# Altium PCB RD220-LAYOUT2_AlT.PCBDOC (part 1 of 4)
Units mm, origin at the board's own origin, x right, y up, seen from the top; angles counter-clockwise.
Board outline 250 x 145 mm, 4 copper layers (TOP, Mid-Layer 1, Mid-Layer 2, BOTTOM), stack 0.711 mm thick; 497 components, 207 nets, 1178 pads, 436 vias.
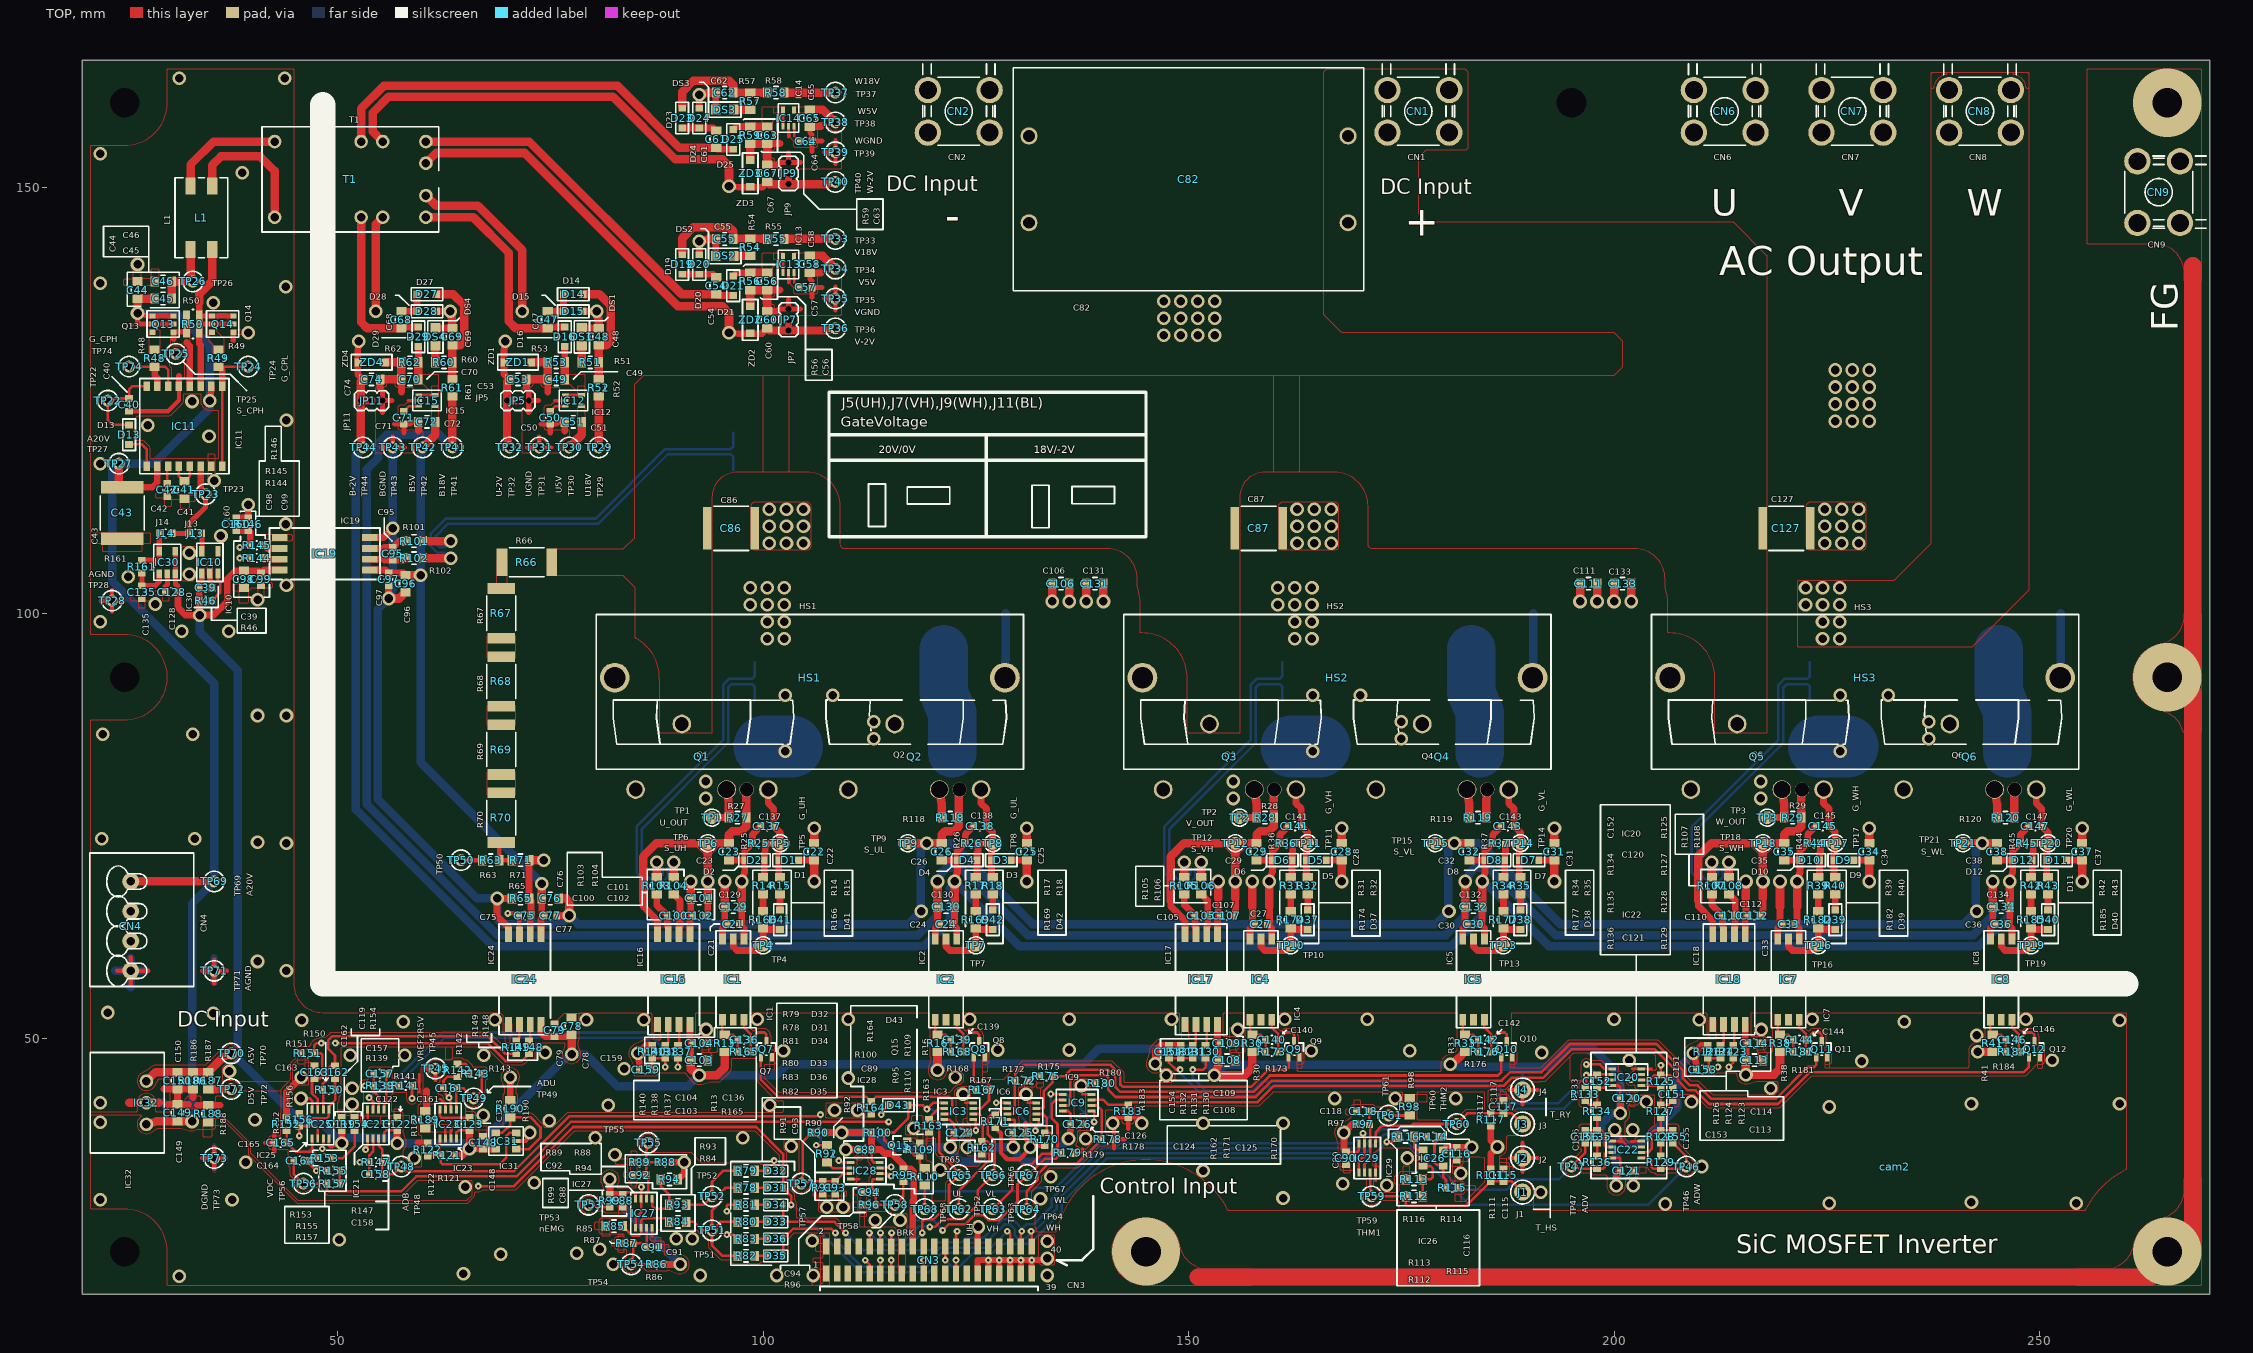
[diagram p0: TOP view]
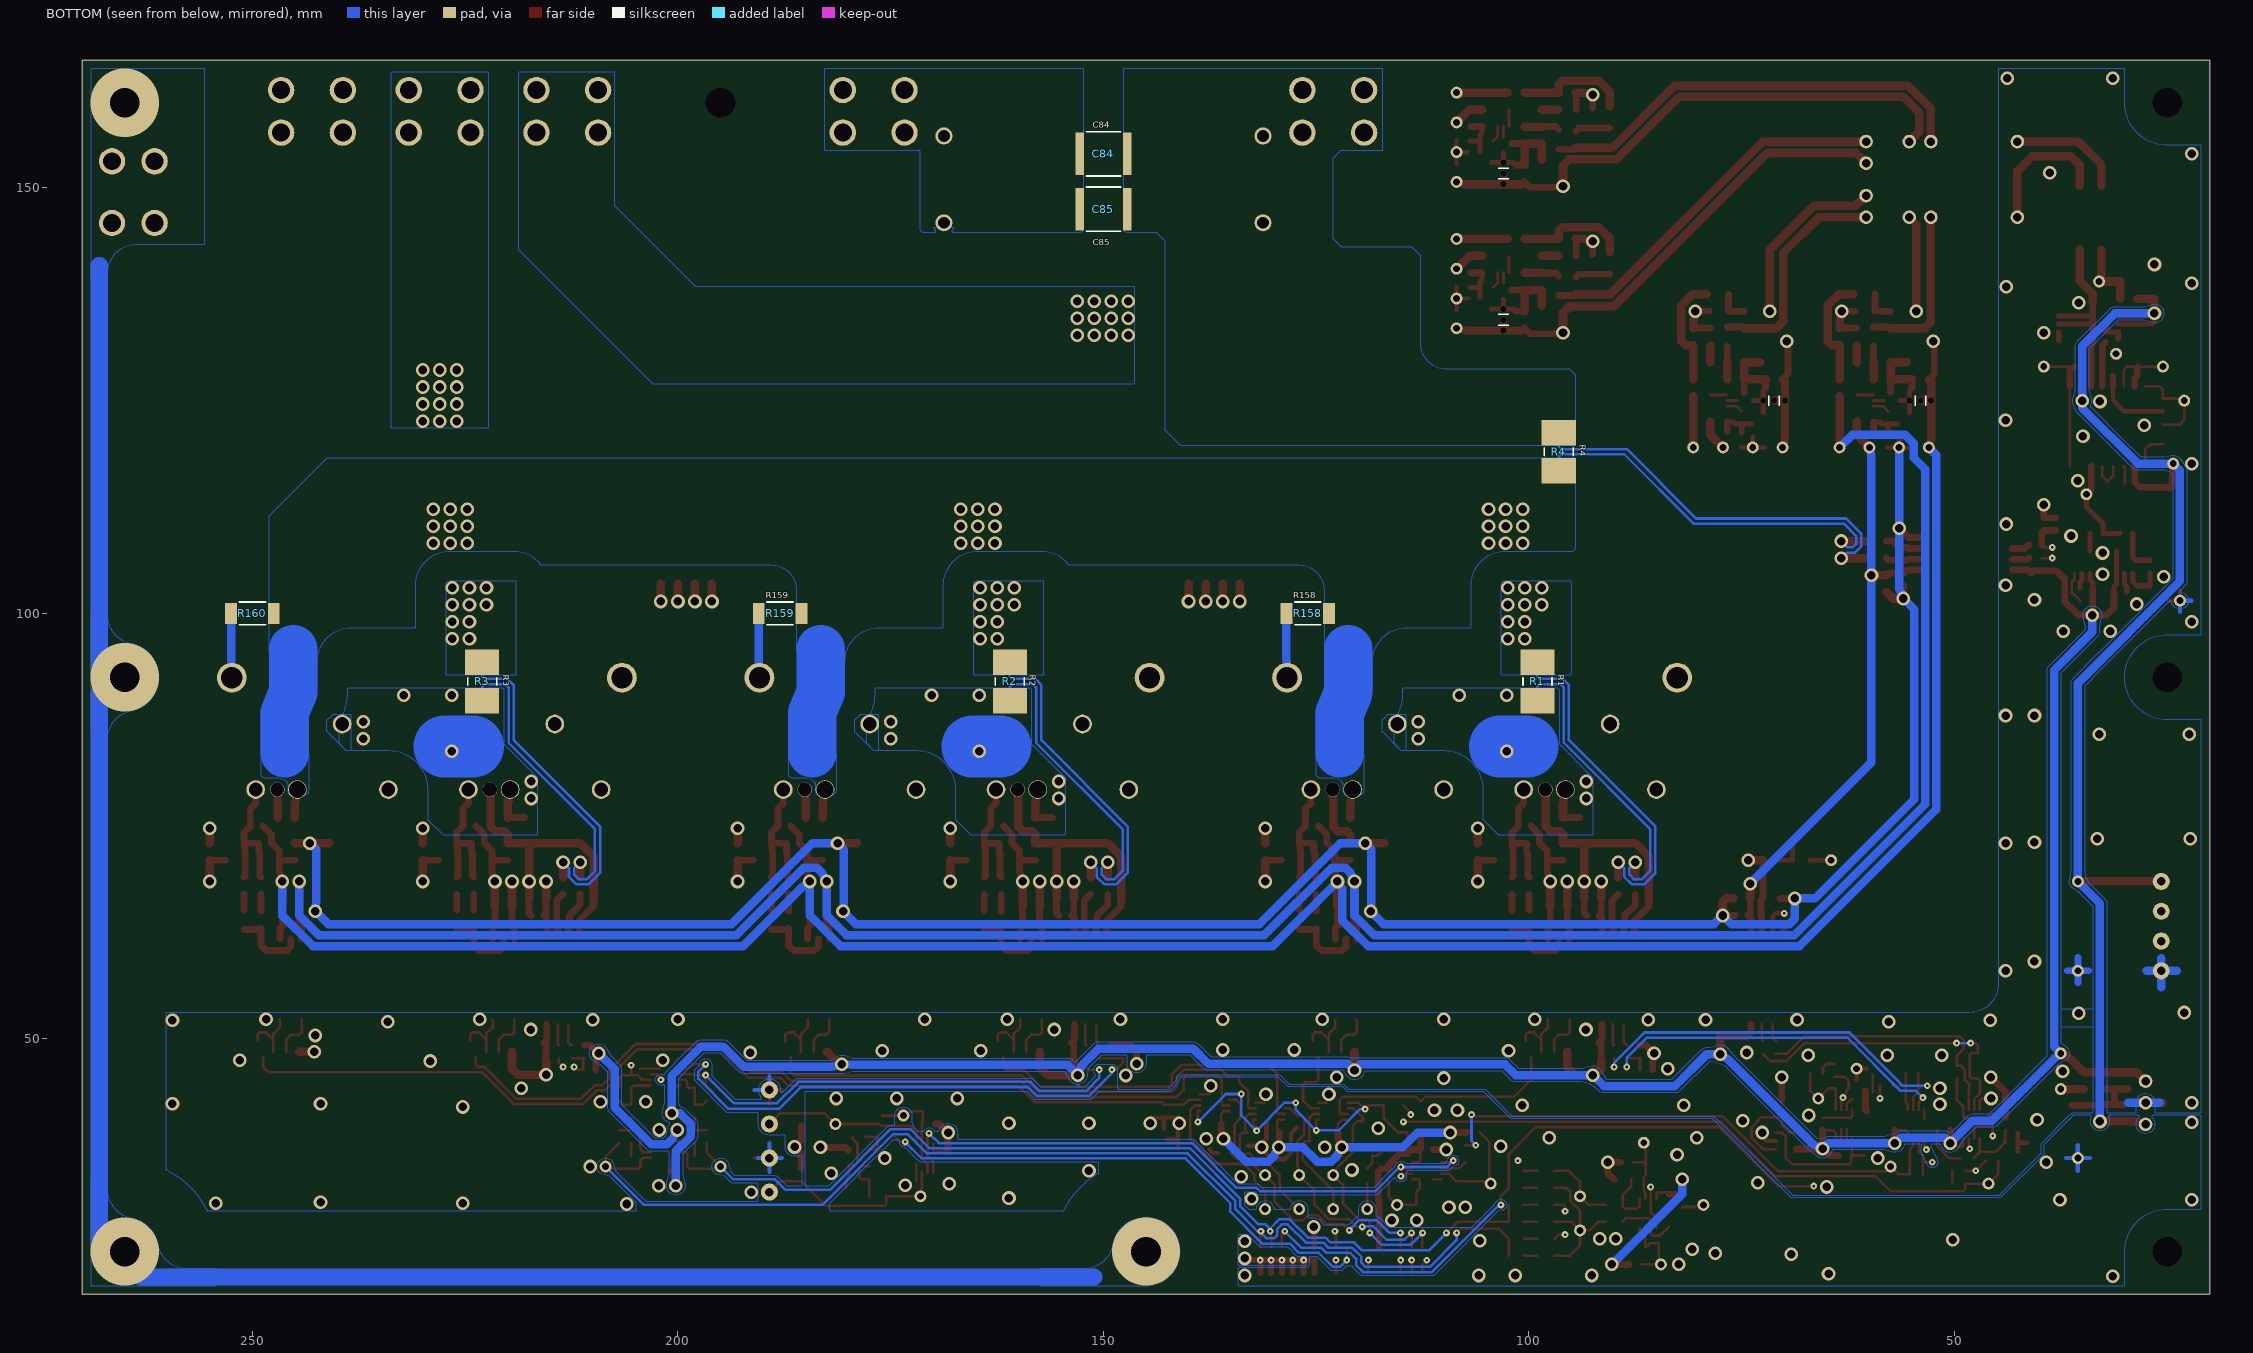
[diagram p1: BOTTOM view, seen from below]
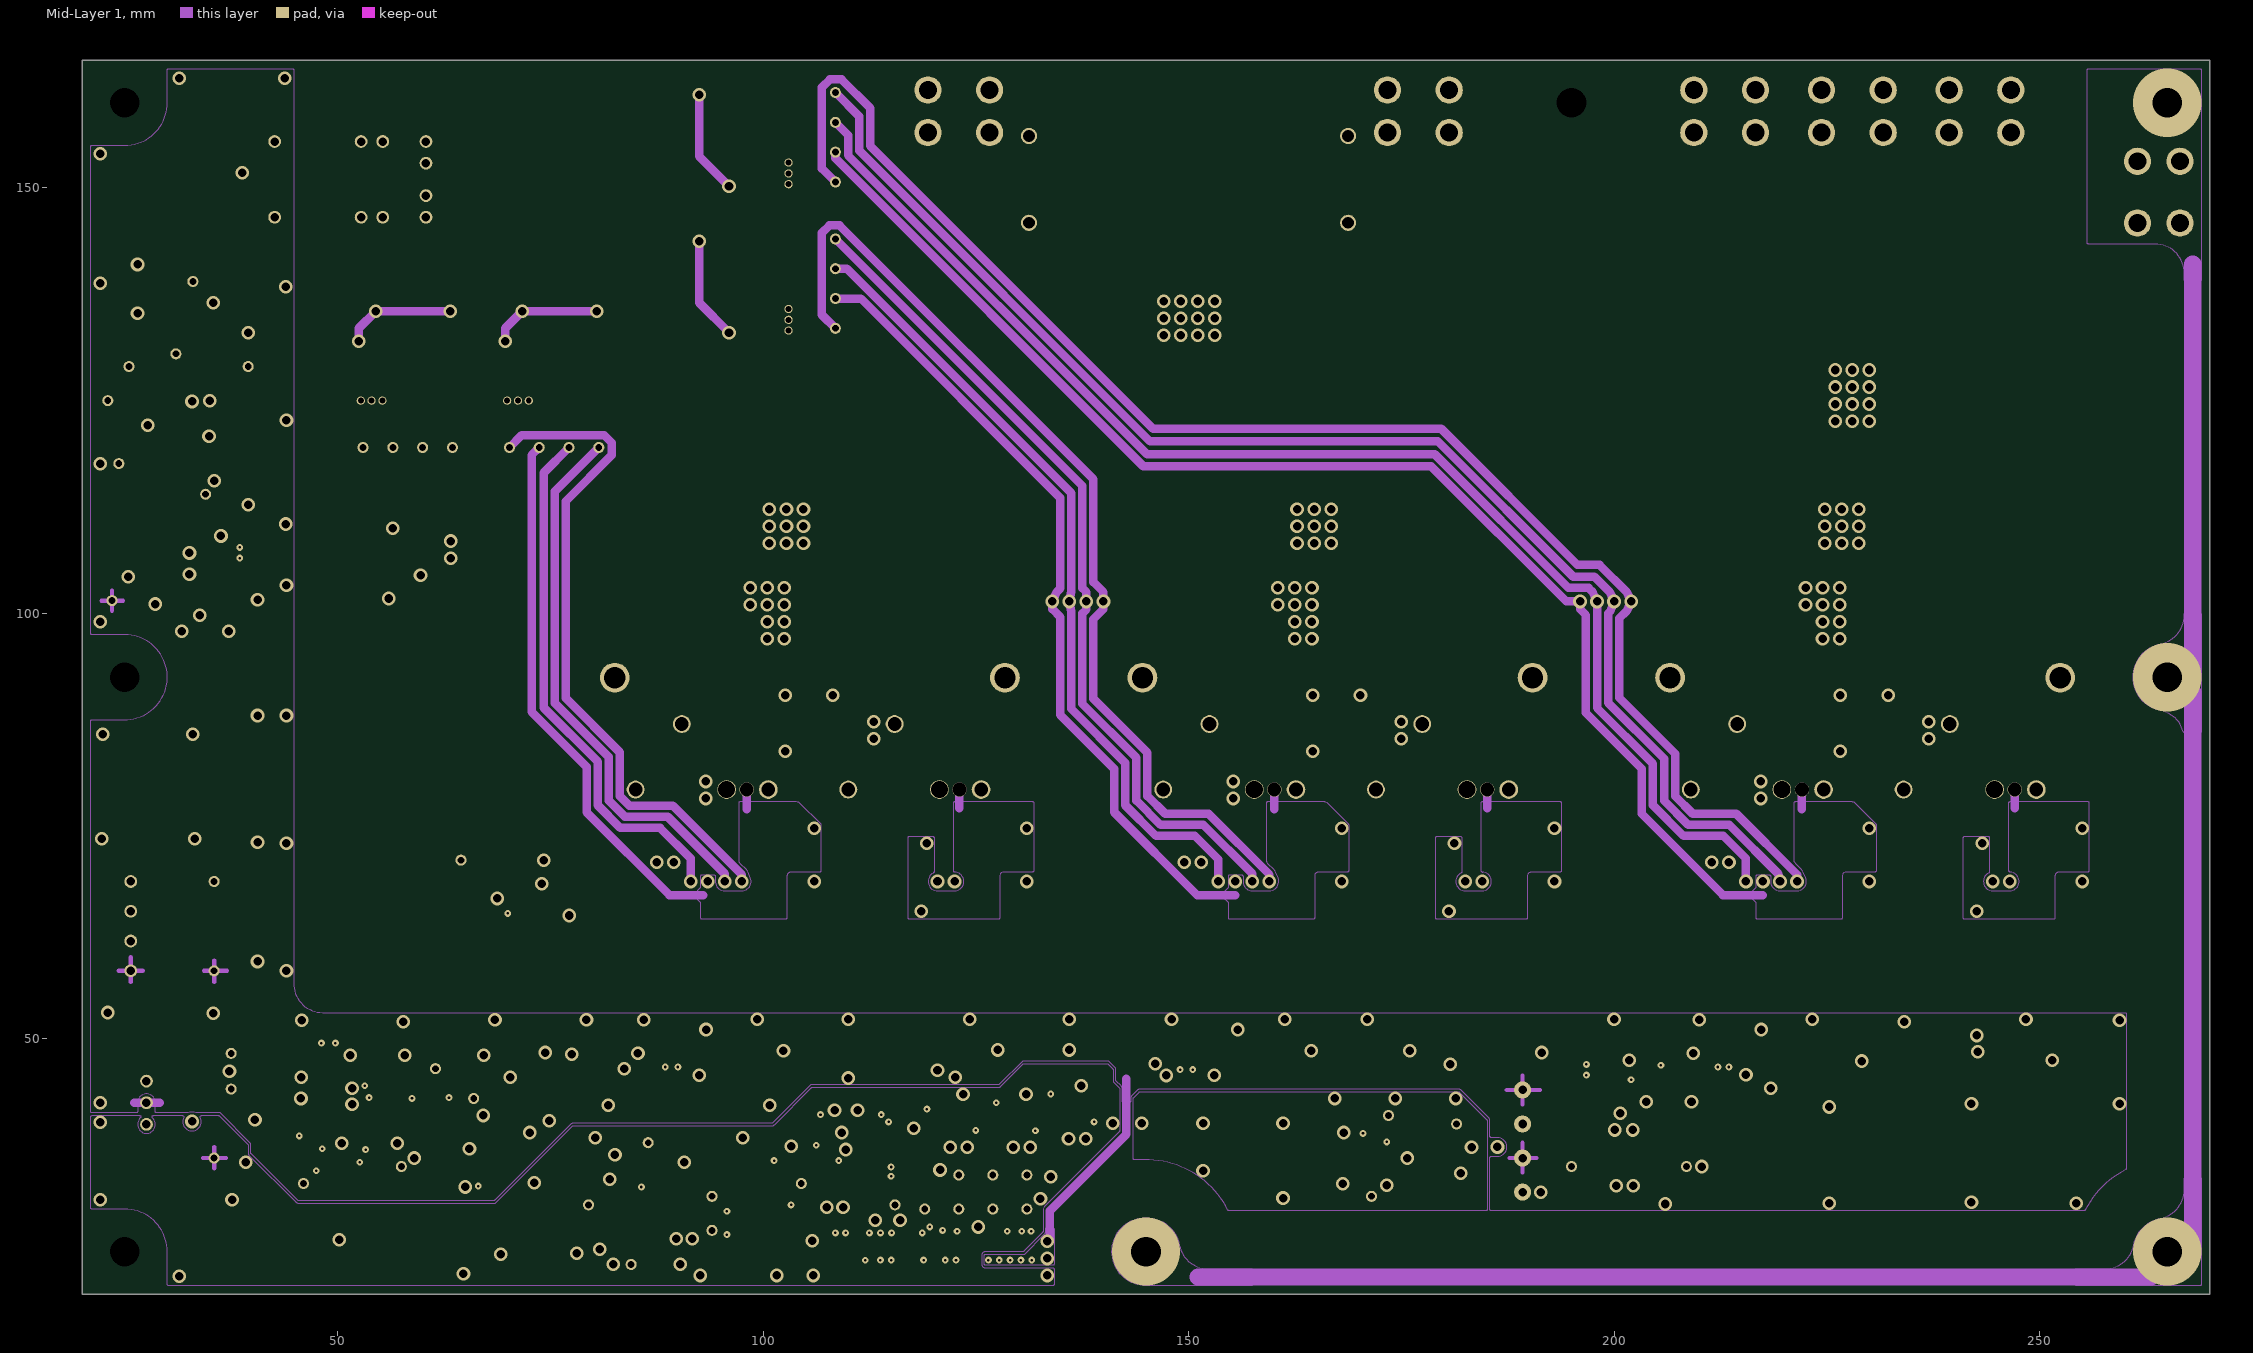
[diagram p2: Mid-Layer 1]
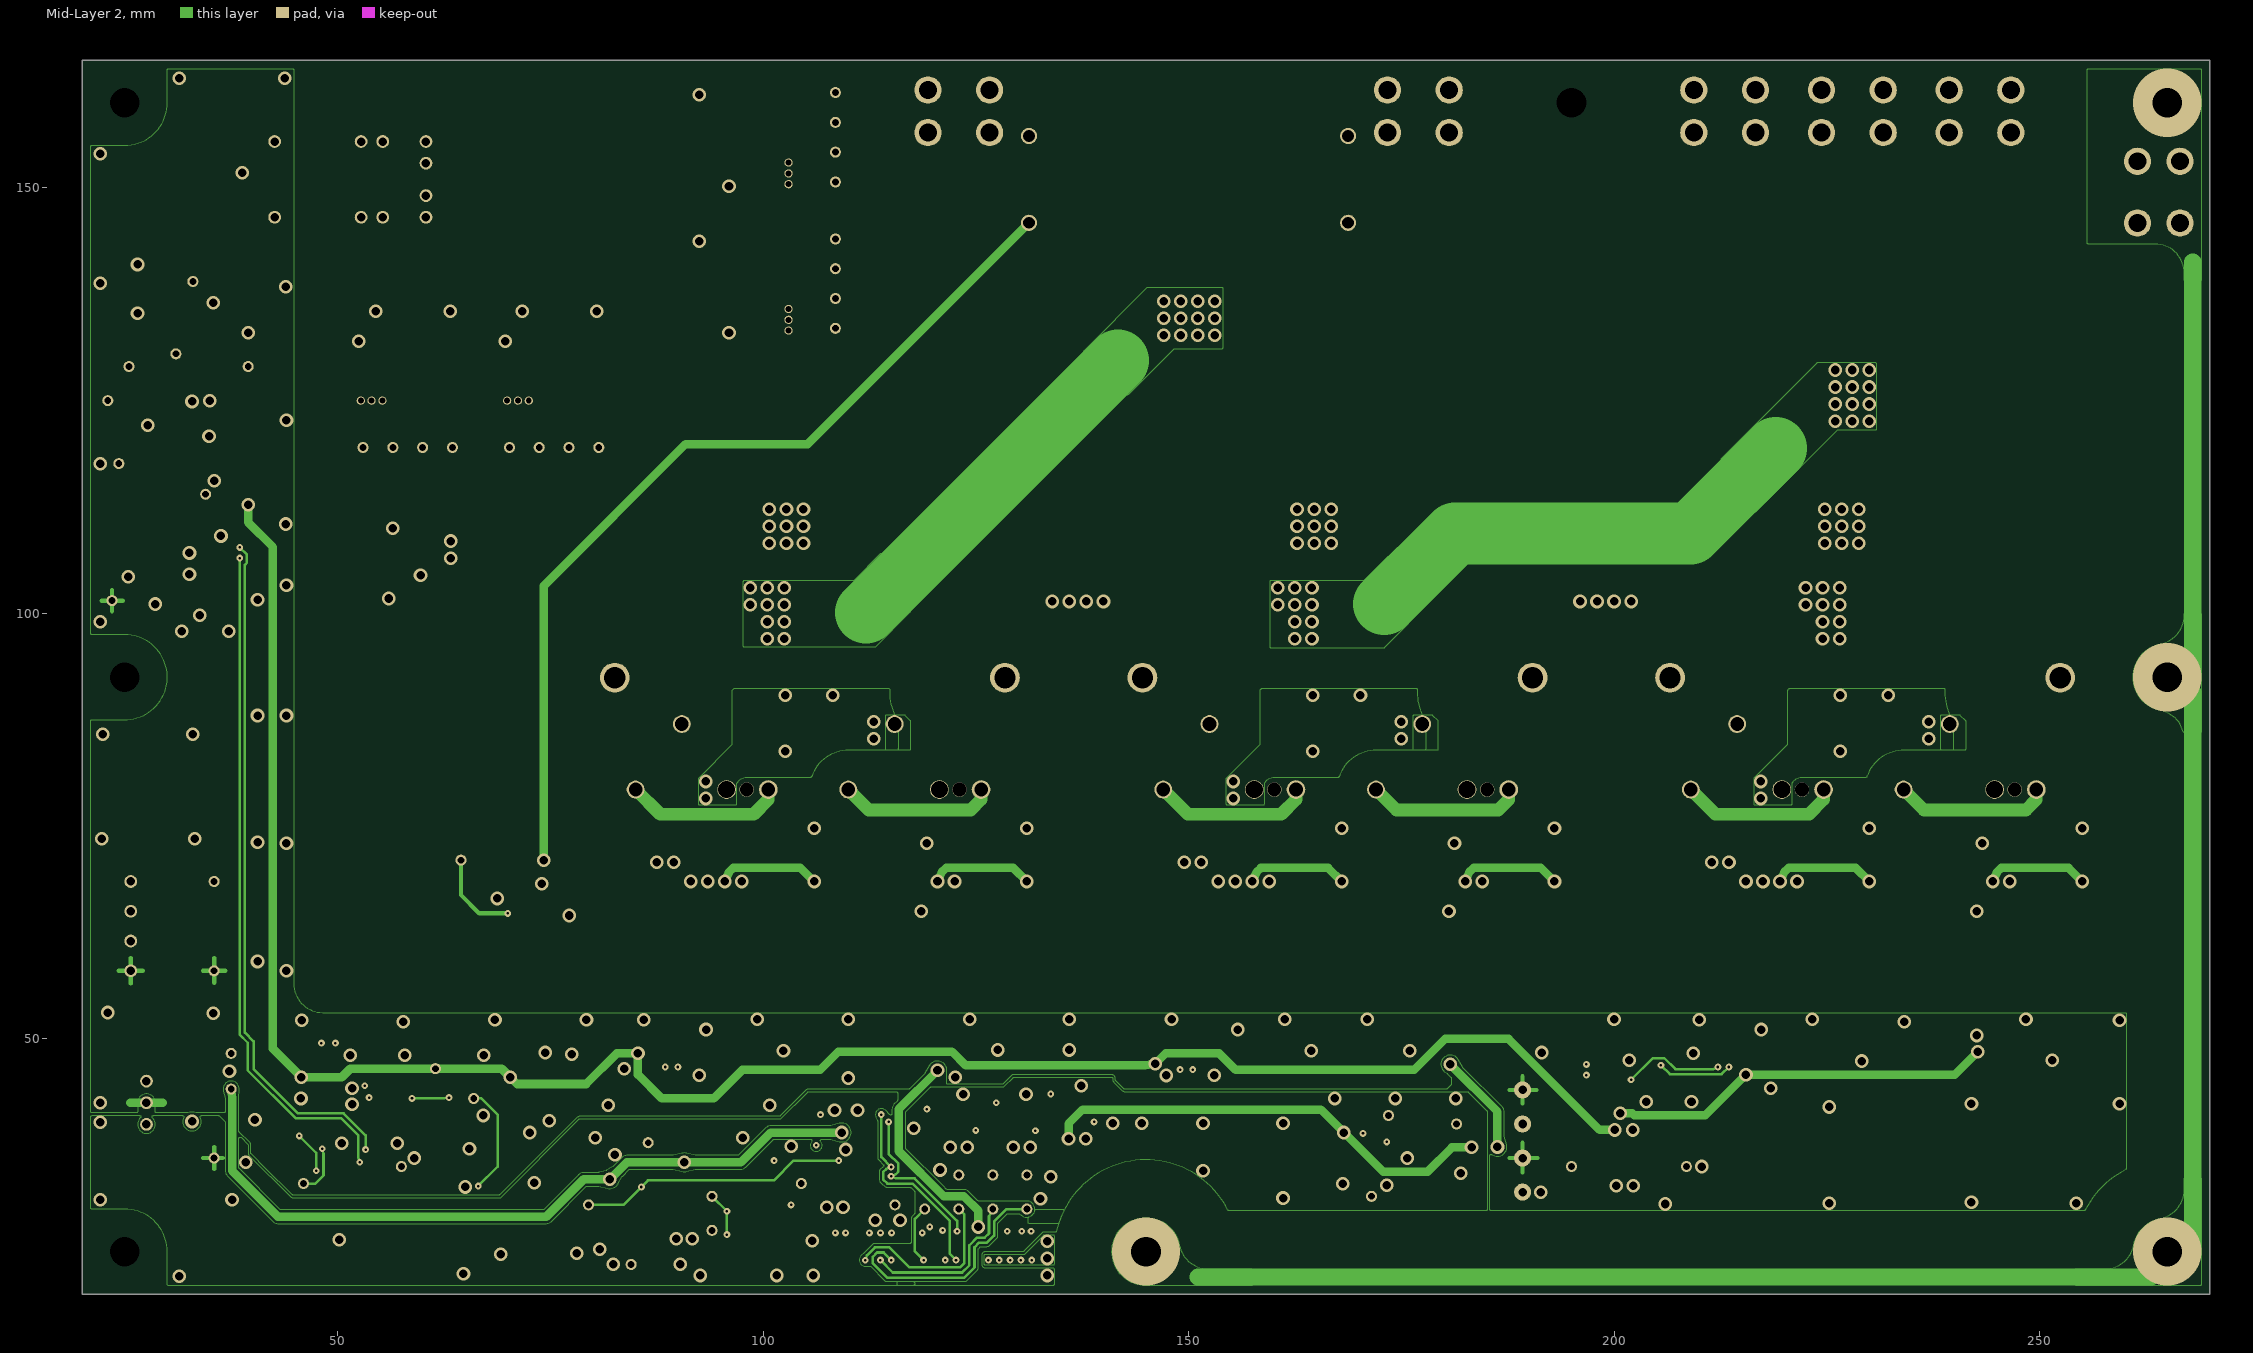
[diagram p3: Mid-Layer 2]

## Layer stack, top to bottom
Top Solder: solder mask 0.0102, Solder Resist, Dk 3.5
TOP: signal copper (thickness not stored)
Mid-Layer 1: signal copper 0.0356
Dielectric2: dielectric 0.32, FR-4, Dk 4.8
Mid-Layer 2: signal copper 0.0356
Dielectric3: dielectric 0.32, FR-4, Dk 4.8
BOTTOM: signal copper (thickness not stored)
Bottom Solder: solder mask 0.0102, Solder Resist, Dk 3.5

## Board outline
20,20 20,165 270,165 270,20

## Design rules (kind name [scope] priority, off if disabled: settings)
AssemblyTestPointUsage [All] p0: scope1count=1 scope1_0_kind=Board scope1_0_value=Board scope2count=1 scope2_0_kind=Board scope2_0_value=Board commentlength=0
AssemblyTestpoint [All] p0: scope1count=1 scope1_0_kind=Board scope1_0_value=Board scope2count=1 scope2_0_kind=Board scope2_0_value=Board commentlength=0
Clearance [All] p0: scope1count=1 scope1_0_kind=Board scope1_0_value=Board scope2count=1 scope2_0_kind=Board scope2_0_value=Board commentlength=0 gap=0.3
Clearance [All] p1: gap=0.3 ignorepadtopadclearanceinfootprint=TRUE except(0.5: Arc-Hole Track-Hole SMDPad-SMDPad SMDPad-Hole THPad-Hole Fill-Hole Poly-Hole Region-Hole Text-Hole; 0.75: Via-Hole; 1: SMDPad-THPad THPad-THPad)
ComponentClearance [All] p0: scope1count=1 scope1_0_kind=Board scope1_0_value=Board scope2count=1 scope2_0_kind=Board scope2_0_value=Board commentlength=0 gap=0.254 collisioncheckmode=3
DiffPairsRouting [All] p0: scope1count=1 scope1_0_kind=Board scope1_0_value=Board scope2count=1 scope2_0_kind=Board scope2_0_value=Board commentlength=0
FabricationTestPointUsage [All] p0: scope1count=1 scope1_0_kind=Board scope1_0_value=Board scope2count=1 scope2_0_kind=Board scope2_0_value=Board commentlength=0 valid=0 allowmultiple=FALSE
FabricationTestpoint [All] p0: scope1count=1 scope1_0_kind=Board scope1_0_value=Board scope2count=1 scope2_0_kind=Board scope2_0_value=Board commentlength=0 side=3 testpointundercomponent=TRUE minsize=1.016 maxsize=2.54 preferedsize=1.524 minholesize=0 maxholesize=1.016 preferedholesize=0.813 testpointgrid=0.025
FanoutControl Fanout_BGA [All] p0 off: scope1count=1 scope1_0_kind=Board scope1_0_value=Board scope2count=1 scope2_0_kind=Board scope2_0_value=Board commentlength=69 // Protel DXP Scope 1 Expression Was: IsBGA   Fanout_BGA (Default Rule)
FanoutControl Fanout_LCC [All] p0 off: scope1count=1 scope1_0_kind=Board scope1_0_value=Board scope2count=1 scope2_0_kind=Board scope2_0_value=Board commentlength=69 // Protel DXP Scope 1 Expression Was: IsLCC   Fanout_LCC (Default Rule)
FanoutControl Fanout_SOIC [All] p0 off: scope1count=1 scope1_0_kind=Board scope1_0_value=Board scope2count=1 scope2_0_kind=Board scope2_0_value=Board commentlength=71 // Protel DXP Scope 1 Expression Was: IsSOIC   Fanout_SOIC (Default Rule)
FanoutControl Fanout_Small [All] p0 off: scope1count=1 scope1_0_kind=Board scope1_0_value=Board scope2count=1 scope2_0_kind=Board scope2_0_value=Board commentlength=84 // Protel DXP Scope 1 Expression Was: (CompPinCount < 5)   Fanout_Small (Default Rule)
FanoutControl Fanout_Default [All] p0: scope1count=1 scope1_0_kind=Board scope1_0_value=Board scope2count=1 scope2_0_kind=Board scope2_0_value=Board commentlength=30 // Fanout_Default (Default Rule)
Height [All] p0: scope1count=1 scope1_0_kind=Board scope1_0_value=Board scope2count=1 scope2_0_kind=Board scope2_0_value=Board commentlength=0
HoleSize [All] p0: scope1count=1 scope1_0_kind=Board scope1_0_value=Board scope2count=1 scope2_0_kind=Board scope2_0_value=Board commentlength=0 absolutevalues=TRUE maxlimit=100 minlimit=0.001 maxpercent=80.000 minpercent=20.000
HoleSize [All] p1: absolutevalues=TRUE maxlimit=100 minlimit=0.001 maxpercent=80.000 minpercent=20.000
HoleToHoleClearance [All] p0: scope1count=1 scope1_0_kind=Board scope1_0_value=Board scope2count=1 scope2_0_kind=Board scope2_0_value=Board commentlength=0
HoleToHoleClearance [All] p1: gap=0.7 allowstackedmicrovias=FALSE
LayerPairs [All] p0: scope1count=1 scope1_0_kind=Board scope1_0_value=Board scope2count=1 scope2_0_kind=Board scope2_0_value=Board commentlength=0 enforce=TRUE
MinimumSolderMaskSliver [All] p0: scope1count=1 scope1_0_kind=Board scope1_0_value=Board scope2count=1 scope2_0_kind=Board scope2_0_value=Board commentlength=0
MinimumSolderMaskSliver [All] p1: minsoldermaskwidth=0.2
NetAntennae [All] p0: scope1count=1 scope1_0_kind=Board scope1_0_value=Board scope2count=1 scope2_0_kind=Board scope2_0_value=Board commentlength=0
NetAntennae [All] p1: netantennaetolerance=100
PasteMaskExpansion [All] p0: scope1count=1 scope1_0_kind=Board scope1_0_value=Board scope2count=1 scope2_0_kind=Board scope2_0_value=Board commentlength=0 expansion=0
PlaneClearance [All] p0: scope1count=1 scope1_0_kind=Board scope1_0_value=Board scope2count=1 scope2_0_kind=Board scope2_0_value=Board commentlength=0 clearance=0.001
PlaneClearance [All] p1: clearance=0.001
PlaneConnect [All] p0: scope1count=1 scope1_0_kind=Board scope1_0_value=Board scope2count=1 scope2_0_kind=Board scope2_0_value=Board commentlength=0 planeconnectstyle=Direct reliefexpansion=0.508 reliefentries=4 reliefconductorwidth=0.254 reliefairgap=0.254
PlaneConnect [All] p1: planeconnectstyle=Direct reliefexpansion=0.508 reliefentries=4 reliefconductorwidth=0.254 reliefairgap=0.254
PolygonConnect [All] p0: scope1count=1 scope1_0_kind=Board scope1_0_value=Board scope2count=1 scope2_0_kind=Board scope2_0_value=Board commentlength=0 connectstyle=Direct reliefconductorwidth=0.254 reliefentries=4 polygonreliefangle="90 Angle"
PolygonConnect [All] p1: connectstyle=Direct reliefconductorwidth=0.254 reliefentries=4 polygonreliefangle="90 Angle" airgapwidth=0.254
RoutingCorners [All] p0: scope1count=1 scope1_0_kind=Board scope1_0_value=Board scope2count=1 scope2_0_kind=Board scope2_0_value=Board commentlength=0 cornerstyle=45-Degree minsetback=2.54 maxsetback=2.54
RoutingLayers [All] p0: scope1count=1 scope1_0_kind=Board scope1_0_value=Board scope2count=1 scope2_0_kind=Board scope2_0_value=Board commentlength=0 top layer=Automatic mid layer 1=Automatic mid layer 2=Automatic bottom layer=Automatic
RoutingPriority [All] p0: scope1count=1 scope1_0_kind=Board scope1_0_value=Board scope2count=1 scope2_0_kind=Board scope2_0_value=Board commentlength=0
RoutingTopology [All] p0: scope1count=1 scope1_0_kind=Board scope1_0_value=Board scope2count=1 scope2_0_kind=Board scope2_0_value=Board commentlength=0 topology=Shortest
RoutingVias [All] p0: scope1count=1 scope1_0_kind=Board scope1_0_value=Board scope2count=1 scope2_0_kind=Board scope2_0_value=Board commentlength=0 holewidth=0.1 width=0.1 viastyle="Through Hole" minholewidth=0.001 minwidth=0.001 maxholewidth=100 maxwidth=100
RoutingVias [All] p1: holewidth=0.1 width=0.1 viastyle="Through Hole" minholewidth=0.001 minwidth=0.001 maxholewidth=100 maxwidth=100
ShortCircuit [All] p0: scope1count=1 scope1_0_kind=Board scope1_0_value=Board scope2count=1 scope2_0_kind=Board scope2_0_value=Board commentlength=0 allowed=FALSE
SilkToBoardRegionClearance [All] p0: scope1count=1 scope1_0_kind=Board scope1_0_value=Board scope2count=1 scope2_0_kind=Board scope2_0_value=Board commentlength=0
SilkToSilkClearance [All] p0: scope1count=1 scope1_0_kind=Board scope1_0_value=Board scope2count=1 scope2_0_kind=Board scope2_0_value=Board commentlength=0
SilkToSilkClearance [All] p1: silktosilkclearance=0.001
SilkToSolderMaskClearance [All] p0 off: scope1count=1 scope1_0_kind=Board scope1_0_value=Board scope2count=1 scope2_0_kind=Board scope2_0_value=Board commentlength=44 // Protel DXP Scope 1 Expression Was: IsPad
SilkToSolderMaskClearance [IsPad] p1: minsilkscreentomaskgap=0.1 clearancetoexposedcopper=TRUE
SolderMaskExpansion [All] p0: scope1count=1 scope1_0_kind=Board scope1_0_value=Board scope2count=1 scope2_0_kind=Board scope2_0_value=Board commentlength=0 expansion=0.001
SolderMaskExpansion [All] p1: expansion=0.001
UnRoutedNet [All] p0: scope1count=1 scope1_0_kind=Board scope1_0_value=Board scope2count=1 scope2_0_kind=Board scope2_0_value=Board commentlength=0
UnpouredPolygon [All] p0: scope1count=1 scope1_0_kind=Board scope1_0_value=Board scope2count=1 scope2_0_kind=Board scope2_0_value=Board commentlength=0
Width [All] p0: scope1count=1 scope1_0_kind=Board scope1_0_value=Board scope2count=1 scope2_0_kind=Board scope2_0_value=Board commentlength=0 maxlimit=1000 minlimit=2539.975 preferedwidth=0
Width [All] p1: maxlimit=1000 minlimit=2539.975 preferedwidth=0 toplayer_minwidth=0 midlayer1_minwidth=0 midlayer2_minwidth=0 bottomlayer_minwidth=0 minimp=50.000000 maximp=50.000000 favimp=50.000000
22 further rules are at their usual default settings.

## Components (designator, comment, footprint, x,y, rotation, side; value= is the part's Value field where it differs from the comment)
C21 "Ta-C0001RR" Ta-C0001RR 96.5,63.5 r180 top
C22 "Ta-C0002RR" Ta-C0002RR 106,72 r270 top
C23 "Ta-C0002RR" Ta-C0002RR 96,72 r90 top
C24 "Ta-C0001RR" Ta-C0001RR 121.5,63.5 r180 top
C25 "Ta-C0002RR" Ta-C0002RR 131,72 r270 top
C26 "Ta-C0002RR" Ta-C0002RR 121,72 r90 top
C27 "Ta-C0001RR" Ta-C0001RR 158.5,63.5 r180 top
C28 "Ta-C0002RR" Ta-C0002RR 168,72 r270 top
C29 "Ta-C0002RR" Ta-C0002RR 158,72 r90 top
C30 "Ta-C0001RR" Ta-C0001RR 183.5,63.5 r180 top
C31 "Ta-C0002RR" Ta-C0002RR 193,72 r270 top
C32 "Ta-C0002RR" Ta-C0002RR 183,72 r90 top
C33 "Ta-C0001RR" Ta-C0001RR 220.5,63.5 r180 top
C34 "Ta-C0002RR" Ta-C0002RR 230,72 r270 top
C35 "Ta-C0002RR" Ta-C0002RR 220,72 r90 top
C36 "Ta-C0001RR" Ta-C0001RR 245.5,63.5 r180 top
C37 "Ta-C0002RR" Ta-C0002RR 255,72 r270 top
C38 "Ta-C0002RR" Ta-C0002RR 245,72 r90 top
C39 "Ta-C0001RR" Ta-C0001RR 34.5,103 r180 top
C40 "Ta-C0001RR" Ta-C0001RR 25.5,124.5 r270 top
C41 "Ta-C0002RR" Ta-C0002RR 32,114.5 r90 top
C42 "Ta-C0001RR" Ta-C0001RR 30,114.5 r90 top
C43 "Ta-C0004RR" Ta-C0004RR 24.7,111.8 r90 top
C44 "Ta-C0002RR" Ta-C0002RR 26.5,138 r270 top
C45 "Ta-C0002RR" Ta-C0002RR 29.5,137 r180 top
C46 "Ta-C0002RR" Ta-C0002RR 29.5,139 r0 top
C47 "Ta-C0002RR" Ta-C0002RR 74.7,134.5 r90 top
C48 "Ta-C0002RR" Ta-C0002RR 80.7,132.5 r270 top
C49 "Ta-C0002RR" Ta-C0002RR 75.7,127.5 r0 top
C50 "Ta-C0001RR" Ta-C0001RR 75,123 r90 top
C51 "Ta-C0002RR" Ta-C0002RR 77.7,122.5 r0 top
C53 "Ta-C0002RR" Ta-C0002RR 71.2,127.5 r0 top
C54 "Ta-C0002RR" Ta-C0002RR 94.5,138.5 r90 top
C55 "Ta-C0002RR" Ta-C0002RR 95.5,144 r0 top
C56 "Ta-C0002RR" Ta-C0002RR 100.5,139 r90 top
C57 "Ta-C0001RR" Ta-C0001RR 105,138.3 r180 top
C58 "Ta-C0002RR" Ta-C0002RR 105.5,141 r90 top
C60 "Ta-C0002RR" Ta-C0002RR 100.5,134.5 r90 top
C61 "Ta-C0002RR" Ta-C0002RR 94.5,155.7 r90 top
C62 "Ta-C0002RR" Ta-C0002RR 95.5,161.2 r0 top
C63 "Ta-C0002RR" Ta-C0002RR 100.5,156.2 r90 top
C64 "Ta-C0001RR" Ta-C0001RR 105,155.5 r180 top
C65 "Ta-C0002RR" Ta-C0002RR 105.5,158.2 r90 top
C67 "Ta-C0002RR" Ta-C0002RR 100.5,151.7 r90 top
C68 "Ta-C0002RR" Ta-C0002RR 57.5,134.5 r90 top
C69 "Ta-C0002RR" Ta-C0002RR 63.5,132.5 r270 top
C70 "Ta-C0002RR" Ta-C0002RR 58.5,127.5 r0 top
C71 "Ta-C0001RR" Ta-C0001RR 57.8,123 r90 top
C72 "Ta-C0002RR" Ta-C0002RR 60.5,122.5 r0 top
C74 "Ta-C0002RR" Ta-C0002RR 54,127.5 r0 top
C75 "Ta-C0001RR" Ta-C0001RR 72,64.5 r180 top
C76 "Ta-C0002RR" Ta-C0002RR 75,66.5 r180 top
C77 "Ta-C0001RR" Ta-C0001RR 75,64.5 r180 top
C78 "Ta-C0002RR" Ta-C0002RR 77.5,51.5 r270 top
C79 "Ta-C0001RR" Ta-C0001RR 75.5,51 r270 top
C82 "Ta-C0004DD-4P" Ta-C0004DD-4P 150,151 r180 top
C84 "Ta-C0003RR" Ta-C0003RR#1 150,154 r180 bottom
C85 "Ta-C0003RR" Ta-C0003RR#1 150,147.5 r180 bottom
C86 "Ta-C0003RR" Ta-C0003RR#2 96.25,110 r180 top
C87 "Ta-C0003RR" Ta-C0003RR#2 158.25,110 r180 top
C88 "Ta-C0001RR" Ta-C0001RR 83.5,31 r90 top
C89 "Ta-C0001RR" Ta-C0001RR 112,37 r0 top
C90 "Ta-C0001RR" Ta-C0001RR 168.5,36 r90 top
C91 "Ta-C0001RR" Ta-C0001RR 87,25.5 r180 top
C92 "Ta-C0001RR" Ta-C0001RR 85.5,34 r0 top
C93 "Ta-C0001RR" Ta-C0001RR 108.5,32.5 r90 top
C94 "Ta-C0001RR" Ta-C0001RR 112.5,32 r0 top
C95 "Ta-C0001RR" Ta-C0001RR 56.5,107 r90 top
C96 "Ta-C0002RR" Ta-C0002RR 58,103.5 r90 top
C97 "Ta-C0001RR" Ta-C0001RR 56,104 r90 top
C98 "Ta-C0002RR" Ta-C0002RR 39,104 r90 top
C99 "Ta-C0001RR" Ta-C0001RR 41,104 r90 top
C100 "Ta-C0001RR" Ta-C0001RR 89.5,64.5 r180 top
C101 "Ta-C0002RR" Ta-C0002RR 92.5,66.5 r180 top
C102 "Ta-C0001RR" Ta-C0001RR 92.5,64.5 r180 top
C103 "Ta-C0002RR" Ta-C0002RR 92.5,47.5 r180 top
C104 "Ta-C0001RR" Ta-C0001RR 92.5,49.5 r180 top
C105 "Ta-C0001RR" Ta-C0001RR 151.5,64.5 r180 top
C106 "Ta-C0002RR" Ta-C0002RR 135,103.5 r0 top
C107 "Ta-C0001RR" Ta-C0001RR 154.5,64.5 r180 top
C108 "Ta-C0002RR" Ta-C0002RR 154.5,47.5 r180 top
C109 "Ta-C0001RR" Ta-C0001RR 154.5,49.5 r180 top
C110 "Ta-C0001RR" Ta-C0001RR 213.5,64.5 r180 top
C111 "Ta-C0002RR" Ta-C0002RR 197,103.5 r0 top
C112 "Ta-C0001RR" Ta-C0001RR 216.5,64.5 r180 top
C113 "Ta-C0002RR" Ta-C0002RR 216.5,47.5 r180 top
C114 "Ta-C0001RR" Ta-C0001RR 216.5,49.5 r180 top
C115 "Ta-C0001RR" Ta-C0001RR 187,34 r270 top
C116 "Ta-C0001RR" Ta-C0001RR 181.5,36.5 r90 top
C117 "Ta-C0001RR" Ta-C0001RR 187,42 r270 top
C118 "Ta-C0001RR" Ta-C0001RR 170.5,41.5 r0 top
C119 "Ta-C0001RR" Ta-C0001RR 50.5,40 r270 top
C120 "Ta-C0001RR" Ta-C0001RR 201.5,43 r180 top
C121 "Ta-C0001RR" Ta-C0001RR 201.5,34.5 r180 top
C122 "Ta-C0001RR" Ta-C0001RR 57,40 r270 top
C123 "Ta-C0001RR" Ta-C0001RR 65.5,40 r270 top
C124 "Ta-C0001RR" Ta-C0001RR 123.2,39 r180 top
C125 "Ta-C0001RR" Ta-C0001RR 130.1,39 r180 top
C126 "Ta-C0001RR" Ta-C0001RR 136.9,40 r180 top
C127 "Ta-C0003RR" Ta-C0003RR#2 220.25,110 r180 top
C128 "Ta-C0001RR" Ta-C0001RR 30.5,102.5 r0 top
C129 "Ta-C0002RR" Ta-C0002RR 96.5,65.5 r180 top
C130 "Ta-C0002RR" Ta-C0002RR 121.5,65.5 r180 top
C131 "Ta-C0002RR" Ta-C0002RR 139,103.5 r180 top
C132 "Ta-C0002RR" Ta-C0002RR 183.5,65.5 r180 top
C133 "Ta-C0002RR" Ta-C0002RR 201,103.5 r180 top
C134 "Ta-C0002RR" Ta-C0002RR 245.5,65.5 r180 top
C135 "Ta-C0001RR" Ta-C0001RR 27,102.5 r90 top
C136 "Ta-C0001RR" Ta-C0001RR 97.8,49.9 r180 top
C137 "Ta-C0001RR" Ta-C0001RR 100.5,75 r0 top
C138 "Ta-C0001RR" Ta-C0001RR 125.5,75 r0 top
C139 "Ta-C0001RR" Ta-C0001RR 122.8,49.9 r180 top
C140 "Ta-C0001RR" Ta-C0001RR 159.8,49.9 r180 top
C141 "Ta-C0001RR" Ta-C0001RR 162.5,75 r0 top
C142 "Ta-C0001RR" Ta-C0001RR 184.8,49.9 r180 top
C143 "Ta-C0001RR" Ta-C0001RR 187.5,75 r0 top
C144 "Ta-C0001RR" Ta-C0001RR 221.8,49.9 r180 top
C145 "Ta-C0001RR" Ta-C0001RR 224.5,75 r0 top
C146 "Ta-C0001RR" Ta-C0001RR 246.8,49.9 r180 top
C147 "Ta-C0001RR" Ta-C0001RR 249.5,75 r0 top
C148 "Ta-C0001RR" Ta-C0001RR 67.1,37.8 r270 top
C149 "Ta-C0002RR" Ta-C0002RR 31.2,41.3 r270 top
C150 "Ta-C0002RR" Ta-C0002RR 31.2,45.1 r90 top
C151 "Ta-C0001RR" Ta-C0001RR 206.9,43.5 r270 top
C152 "Ta-C0001RR" Ta-C0001RR 198,45 r270 top
C153 "Ta-C0001RR" Ta-C0001RR 210.4,46.4 r0 top
C154 "Ta-C0001RR" Ta-C0001RR 147.7,48.5 r270 top
C155 "Ta-C0001RR" Ta-C0001RR 206.9,38.5 r270 top
C156 "Ta-C0001RR" Ta-C0001RR 196.6,38.5 r270 top
C157 "Ta-C0001RR" Ta-C0001RR 55,45.9 r0 top
C158 "Ta-C0001RR" Ta-C0001RR 54.5,34.1 r0 top
C159 "Ta-C0001RR" Ta-C0001RR 86.2,46.4 r0 top
C160 "Ta-C0001RR" Ta-C0001RR 38.1,110.5 r270 top
C161 "Ta-C0001RR" Ta-C0001RR 63.2,44.2 r0 top
C162 "Ta-C0001RR" Ta-C0001RR 49.7,46.1 r270 top
C163 "Ta-C0001RR" Ta-C0001RR 47.3,46.1 r270 top
C164 "Ta-C0001RR" Ta-C0001RR 45.6,35.7 r180 top
C165 "Ta-C0001RR" Ta-C0001RR 43.3,37.8 r180 top
cam2 "Logo-Toshiba" Logo-Toshiba 233,35 r0 top
CN1 "Ta-CN0004DD(OT-005+OT-006)" Ta-CN0004DD(OT-005+OT-006) 177,159 r90 top
CN2 "Ta-CN0004DD(OT-005+OT-006)" Ta-CN0004DD(OT-005+OT-006) 123,159 r90 top
CN3 "Ta-CN0005DDFy" Ta-CN0005DDFy 119.5,19.556 r180 top
CN4 "Ta-CN0002DD" Ta-CN0002DD 27,64 r270 top
CN6 "Ta-CN0004DD(OT-005+OT-006)" Ta-CN0004DD(OT-005+OT-006) 213,159 r90 top
CN7 "Ta-CN0004DD(OT-005+OT-006)" Ta-CN0004DD(OT-005+OT-006) 228,159 r90 top
CN8 "Ta-CN0004DD(OT-005+OT-006)" Ta-CN0004DD(OT-005+OT-006) 243,159 r90 top
CN9 "Ta-CN0004DD(OT-005+OT-006)" Ta-CN0004DD(OT-005+OT-006) 264,149.5 r0 top
D1 "Ta-D0002RR" Ta-D0002RR 103,71 r180 top
D2 "Ta-D0002RR" Ta-D0002RR 99,71 r180 top
D3 "Ta-D0002RR" Ta-D0002RR 128,71 r180 top
D4 "Ta-D0002RR" Ta-D0002RR 124,71 r180 top
D5 "Ta-D0002RR" Ta-D0002RR 165,71 r180 top
D6 "Ta-D0002RR" Ta-D0002RR 161,71 r180 top
D7 "Ta-D0002RR" Ta-D0002RR 190,71 r180 top
D8 "Ta-D0002RR" Ta-D0002RR 186,71 r180 top
D9 "Ta-D0002RR" Ta-D0002RR 227,71 r180 top
D10 "Ta-D0002RR" Ta-D0002RR 223,71 r180 top
D11 "Ta-D0002RR" Ta-D0002RR 252,71 r180 top
D12 "Ta-D0002RR" Ta-D0002RR 248,71 r180 top
D13 "Ta-D0002RR" Ta-D0002RR 25.5,121 r270 top
D14 "Ta-D0002RR" Ta-D0002RR 77.7,137.5 r180 top
D15 "Ta-D0002RR" Ta-D0002RR 77.7,135.5 r0 top
D16 "Ta-D0002RR" Ta-D0002RR 76.7,132.5 r90 top
D19 "Ta-D0002RR" Ta-D0002RR 90.5,141 r270 top
D20 "Ta-D0002RR" Ta-D0002RR 92.5,141 r90 top
D21 "Ta-D0002RR" Ta-D0002RR 96.5,138.5 r270 top
D23 "Ta-D0002RR" Ta-D0002RR 90.5,158.2 r270 top
D24 "Ta-D0002RR" Ta-D0002RR 92.5,158.2 r90 top
D25 "Ta-D0002RR" Ta-D0002RR 96.5,155.7 r270 top
D27 "Ta-D0002RR" Ta-D0002RR 60.5,137.5 r180 top
D28 "Ta-D0002RR" Ta-D0002RR 60.5,135.5 r0 top
D29 "Ta-D0002RR" Ta-D0002RR 59.5,132.5 r90 top
D31 "Ta-D0001RR" Ta-D0001RR 101.5,32.5 r0 top
D32 "Ta-D0001RR" Ta-D0001RR 101.5,34.5 r180 top
D33 "Ta-D0001RR" Ta-D0001RR 101.5,28.5 r0 top
D34 "Ta-D0001RR" Ta-D0001RR 101.5,30.5 r180 top
D35 "Ta-D0001RR" Ta-D0001RR 101.5,24.5 r0 top
D36 "Ta-D0001RR" Ta-D0001RR 101.5,26.5 r180 top
D37 "Ta-D0002RR" Ta-D0002RR 164,64 r90 top
D38 "Ta-D0002RR" Ta-D0002RR 189,64 r90 top
D39 "Ta-D0002RR" Ta-D0002RR 226,64 r90 top
D40 "Ta-D0002RR" Ta-D0002RR 251,64 r90 top
D41 "Ta-D0002RR" Ta-D0002RR 102,64 r90 top
D42 "Ta-D0002RR" Ta-D0002RR 127,64 r90 top
D43 "Ta-D0002RR" Ta-D0002RR 115.9,42.2 r0 top
DS1 "Ta-LED0001RR" Ta-LED0001RR 78.7,132.5 r270 top
DS2 "Ta-LED0001RR" Ta-LED0001RR 95.5,142 r0 top
DS3 "Ta-LED0001RR" Ta-LED0001RR 95.5,159.2 r0 top
DS4 "Ta-LED0001RR" Ta-LED0001RR 61.5,132.5 r270 top
HS1 "Ta-ETC0005DD" Ta-ETC0005DD 105.5,90 r0 top
HS2 "Ta-ETC0005DD" Ta-ETC0005DD 167.5,90 r0 top
HS3 "Ta-ETC0005DD" Ta-ETC0005DD 229.5,90 r0 top
IC1 "Ta-IC0007RR" Ta-IC0007RR 96.5,57 r0 top
IC2 "Ta-IC0007RR" Ta-IC0007RR 121.5,57 r0 top
IC3 "Ta-IC0009RR_70" Ta-IC0009RR_70 123,41.5 r90 top
IC4 "Ta-IC0007RR" Ta-IC0007RR 158.5,57 r0 top
IC5 "Ta-IC0007RR" Ta-IC0007RR 183.5,57 r0 top
IC6 "Ta-IC0009RR_70" Ta-IC0009RR_70 130.4,41.5 r90 top
IC7 "Ta-IC0007RR" Ta-IC0007RR 220.5,57 r0 top
IC8 "Ta-IC0007RR" Ta-IC0007RR 245.5,57 r0 top
IC9 "Ta-IC0009RR_70" Ta-IC0009RR_70 136.9,42.5 r90 top
IC10 "Ta-IC0004RR" Ta-IC0004RR 35,106 r0 top
IC11 "Ta-IC0003RR" Ta-IC0003RR 32,122 r0 top
IC12 "Ta-IC0008RR_70" Ta-IC0008RR_70 77.7,125 r270 top
IC13 "Ta-IC0008RR_70" Ta-IC0008RR_70 103,141 r0 top
IC14 "Ta-IC0008RR_70" Ta-IC0008RR_70 103,158.2 r0 top
IC15 "Ta-IC0008RR_70" Ta-IC0008RR_70 60.5,125 r270 top
IC16 "Ta-IC0001RR" Ta-IC0001RR 89.5,57 r180 top
IC17 "Ta-IC0001RR" Ta-IC0001RR 151.5,57 r180 top
IC18 "Ta-IC0001RR" Ta-IC0001RR 213.5,57 r180 top
IC19 "Ta-IC0001RR" Ta-IC0001RR 48.5,107 r90 top
IC20 "Ta-IC0009RR_70" Ta-IC0009RR_70 201.5,45.5 r90 top
IC21 "Ta-IC0009RR_70" Ta-IC0009RR_70 54.5,40 r180 top
IC22 "Ta-IC0009RR_70" Ta-IC0009RR_70 201.5,37 r90 top
IC23 "Ta-IC0009RR_70" Ta-IC0009RR_70 63,40 r180 top
IC24 "Ta-IC0001RR" Ta-IC0001RR 72,57 r180 top
IC25 "Ta-IC0009RR_70" Ta-IC0009RR_70 48,40 r180 top
IC26 "Ta-IC0005RR_70" Ta-IC0005RR_70 178.75,36 r270 top
IC27 "Ta-IC0009RR_70" Ta-IC0009RR_70 86,29.5 r0 top
IC28 "Ta-IC0009RR_70" Ta-IC0009RR_70 112,34.5 r270 top
IC29 "Ta-IC0009RR_70" Ta-IC0009RR_70 171,36 r0 top
IC30 "Ta-IC0010RR_70" Ta-IC0010RR_70 30,106 r0 top
IC31 "Ta-IC0005RR_70" Ta-IC0005RR_70 69.8,38 r90 top
IC32 "Ta-IC0001DD" Ta-IC0001DD 25.3,42.5 r90 top
J1 "Ta-ETC0003DD" Ta-ETC0003DD 189.25,32 r180 top
J2 "Ta-ETC0003DD" Ta-ETC0003DD 189.25,36 r180 top
J3 "Ta-ETC0003DD" Ta-ETC0003DD 189.25,40 r180 top
J4 "Ta-ETC0003DD" Ta-ETC0003DD 189.25,44 r180 top
J13 "Ta-R0005RR" Ta-R0005RR 33.3,109.4 r180 top
J14 "Ta-R0005RR" Ta-R0005RR 29.8,109.4 r0 top
JP5 "Ta-J0002DD" Ta-J0002DD 71.2,125 r0 top
JP7 "Ta-J0002DD" Ta-J0002DD 103,134.5 r270 top
JP9 "Ta-J0002DD" Ta-J0002DD 103,151.7 r270 top
JP11 "Ta-J0002DD" Ta-J0002DD 54,125 r0 top
L1 "Ta-L0001RRM" Ta-L0001RRM 34,146.5 r90 top
Q1 "Ta-ETC0001DDFy" Ta-ETC0001DDFy 93,87 r0 top
Q2 "Ta-ETC0001DDFy" Ta-ETC0001DDFy 118,87 r0 top
Q3 "Ta-ETC0001DDFy" Ta-ETC0001DDFy 155,87 r0 top
Q4 "Ta-ETC0001DDFy" Ta-ETC0001DDFy 180,87 r0 top
Q5 "Ta-ETC0001DDFy" Ta-ETC0001DDFy 217,87 r0 top
Q6 "Ta-ETC0001DDFy" Ta-ETC0001DDFy 242,87 r0 top
Q7 "Ta-FET0001RR" Ta-FET0001RR 100.4,48.8 r0 top
Q8 "Ta-FET0001RR" Ta-FET0001RR 125.4,48.8 r0 top
Q9 "Ta-FET0001RR" Ta-FET0001RR 162.4,48.8 r0 top
Q10 "Ta-FET0001RR" Ta-FET0001RR 187.4,48.8 r0 top
Q11 "Ta-FET0001RR" Ta-FET0001RR 224.4,48.8 r0 top
Q12 "Ta-FET0001RR" Ta-FET0001RR 249.4,48.8 r0 top
Q13 "Ta-FET0002RR" Ta-FET0002RR 29.5,134 r270 top
Q14 "Ta-FET0002RR" Ta-FET0002RR 36.5,134 r270 top
Q15 "Ta-FET0001RR" Ta-FET0001RR 116,37.5 r90 top
R1 "Ta-R0001RR_F" Ta-R0001RR_F 99,92 r270 bottom
R2 "Ta-R0001RR_F" Ta-R0001RR_F 161,92 r270 bottom
R3 "Ta-R0001RR_F" Ta-R0001RR_F 223,92 r270 bottom
R4 "Ta-R0001RR_F" Ta-R0001RR_F 96.5,119 r90 bottom
R13 "Ta-R0003RR" Ta-R0003RR 95.5,49.5 r270 top
R14 "Ta-R0003RR" Ta-R0003RR 100,68 r270 top
R15 "Ta-R0003RR" Ta-R0003RR 102,68 r270 top
R16 "Ta-R0003RR" Ta-R0003RR 120.5,49.5 r270 top
R17 "Ta-R0003RR" Ta-R0003RR 125,68 r270 top
R18 "Ta-R0003RR" Ta-R0003RR 127,68 r270 top
R25 "Ta-R0005RR" Ta-R0005RR 99.5,73 r180 top
R26 "Ta-R0005RR" Ta-R0005RR 124.5,73 r180 top
R27 "Ta-R0003RR" Ta-R0003RR 97,76 r180 top
R28 "Ta-R0003RR" Ta-R0003RR 159,76 r180 top
R29 "Ta-R0003RR" Ta-R0003RR 221,76 r180 top
R30 "Ta-R0003RR" Ta-R0003RR 157.5,49.5 r270 top
R31 "Ta-R0003RR" Ta-R0003RR 162,68 r270 top
R32 "Ta-R0003RR" Ta-R0003RR 164,68 r270 top
R33 "Ta-R0003RR" Ta-R0003RR 182.5,49.5 r270 top
R34 "Ta-R0003RR" Ta-R0003RR 187,68 r270 top
R35 "Ta-R0003RR" Ta-R0003RR 189,68 r270 top
R36 "Ta-R0005RR" Ta-R0005RR 161.5,73 r180 top
R37 "Ta-R0005RR" Ta-R0005RR 186.5,73 r180 top
R38 "Ta-R0003RR" Ta-R0003RR 219.5,49.5 r270 top
R39 "Ta-R0003RR" Ta-R0003RR 224,68 r270 top
R40 "Ta-R0003RR" Ta-R0003RR 226,68 r270 top
R41 "Ta-R0003RR" Ta-R0003RR 244.5,49.5 r270 top
R42 "Ta-R0003RR" Ta-R0003RR 249,68 r270 top
R43 "Ta-R0003RR" Ta-R0003RR 251,68 r270 top
R44 "Ta-R0005RR" Ta-R0005RR 223.5,73 r180 top
R45 "Ta-R0005RR" Ta-R0005RR 248.5,73 r180 top
R46 "Ta-R0005RR" Ta-R0005RR 34.5,101.5 r180 top
R48 "Ta-R0003RR" Ta-R0003RR 28.5,130 r90 top
R49 "Ta-R0003RR" Ta-R0003RR 36,130 r90 top
R50 "Ta-R0006RR" Ta-R0006RR 33,134 r180 top
R51 "Ta-R0003RR" Ta-R0003RR 79.7,129.5 r0 top
R52 "Ta-R0003RR" Ta-R0003RR 80.7,126.5 r270 top
R53 "Ta-R0003RR" Ta-R0003RR 75.7,129.5 r0 top
R54 "Ta-R0003RR" Ta-R0003RR 98.5,143 r90 top
R55 "Ta-R0003RR" Ta-R0003RR 101.5,144 r0 top
R56 "Ta-R0003RR" Ta-R0003RR 98.5,139 r90 top
R57 "Ta-R0003RR" Ta-R0003RR 98.5,160.2 r90 top
R58 "Ta-R0003RR" Ta-R0003RR 101.5,161.2 r0 top
R59 "Ta-R0003RR" Ta-R0003RR 98.5,156.2 r90 top
R60 "Ta-R0003RR" Ta-R0003RR 62.5,129.5 r0 top
R61 "Ta-R0003RR" Ta-R0003RR 63.5,126.5 r270 top
R62 "Ta-R0003RR" Ta-R0003RR 58.5,129.5 r0 top
R63 "Ta-R0003RR" Ta-R0003RR 68,71 r0 top
R65 "Ta-R0003RR" Ta-R0003RR 71.5,66.5 r0 top
R66 "Ta-R0007RR" Ta-R0007RR 72.25,106 r180 top
R67 "Ta-R0007RR" Ta-R0007RR 69.25,100 r270 top
R68 "Ta-R0007RR" Ta-R0007RR 69.25,92 r270 top
R69 "Ta-R0007RR" Ta-R0007RR 69.25,84 r270 top
R70 "Ta-R0007RR" Ta-R0007RR 69.25,76 r270 top
R71 "Ta-R0003RR" Ta-R0003RR 71.5,71 r0 top
R78 "Ta-R0003RR" Ta-R0003RR 98,32.5 r0 top
R79 "Ta-R0003RR" Ta-R0003RR 98,34.5 r0 top
R80 "Ta-R0003RR" Ta-R0003RR 98,28.5 r0 top
R81 "Ta-R0003RR" Ta-R0003RR 98,30.5 r0 top
R82 "Ta-R0003RR" Ta-R0003RR 98,24.5 r0 top
R83 "Ta-R0003RR" Ta-R0003RR 98,26.5 r0 top
R84 "Ta-R0003RR" Ta-R0003RR 90,28.5 r0 top
R85 "Ta-R0003RR" Ta-R0003RR 82.5,28 r180 top
R86 "Ta-R0005RR" Ta-R0005RR 87.5,23.5 r180 top
R87 "Ta-R0005RR" Ta-R0005RR 84,26 r180 top
R88 "Ta-R0005RR" Ta-R0005RR 88.5,35.5 r180 top
R89 "Ta-R0005RR" Ta-R0005RR 85.5,35.5 r180 top
R90 "Ta-R0005RR" Ta-R0005RR 106.5,39 r180 top
R91 "Ta-R0005RR" Ta-R0005RR 107,32.5 r270 top
R92 "Ta-R0003RR" Ta-R0003RR 107.5,36.5 r90 top
R93 "Ta-R0003RR" Ta-R0003RR 90,30.5 r0 top
R94 "Ta-R0003RR" Ta-R0003RR 89,33.5 r180 top
R95 "Ta-R0005RR" Ta-R0005RR 116.5,34 r270 top
R96 "Ta-R0005RR" Ta-R0005RR 112.5,30.5 r180 top
R97 "Ta-R0005RR" Ta-R0005RR 170.5,40 r0 top
R98 "Ta-R0003RR" Ta-R0003RR 176,42 r90 top
R99 "Ta-R0005RR" Ta-R0005RR 82,31 r270 top
R100 "Ta-R0005RR" Ta-R0005RR 113.5,39 r0 top
R101 "Ta-R0003RR" Ta-R0003RR 59,108.5 r0 top
R102 "Ta-R0003RR" Ta-R0003RR 59,106.5 r0 top
R103 "Ta-R0003RR" Ta-R0003RR 87.5,68 r90 top
R104 "Ta-R0003RR" Ta-R0003RR 89.5,68 r90 top
R105 "Ta-R0003RR" Ta-R0003RR 149.5,68 r90 top
R106 "Ta-R0003RR" Ta-R0003RR 151.5,68 r90 top
R107 "Ta-R0003RR" Ta-R0003RR 211.5,68 r90 top
R108 "Ta-R0003RR" Ta-R0003RR 213.5,68 r90 top
R109 "Ta-R0005RR" Ta-R0005RR 118.4,37 r90 top
R110 "Ta-R0003RR" Ta-R0003RR 119,33.8 r270 top
R111 "Ta-R0005RR" Ta-R0005RR 185.5,34 r270 top
R112 "Ta-R0003RR" Ta-R0003RR 176.5,31.5 r0 top
R113 "Ta-R0003RR" Ta-R0003RR 176.5,33.5 r180 top
R114 "Ta-R0005RR" Ta-R0005RR 178.75,38.5 r0 top
R115 "Ta-R0005RR" Ta-R0005RR 181,32.5 r180 top
R116 "Ta-R0003RR" Ta-R0003RR 175.5,38.5 r180 top
R117 "Ta-R0005RR" Ta-R0005RR 185.5,40.5 r90 top
R118 "Ta-R0003RR" Ta-R0003RR 122,76 r180 top
R119 "Ta-R0003RR" Ta-R0003RR 184,76 r180 top
R120 "Ta-R0003RR" Ta-R0003RR 246,76 r180 top
R121 "Ta-R0005RR" Ta-R0005RR 62.9,36.3 r180 top
R122 "Ta-R0005RR" Ta-R0005RR 60.6,37 r90 top
R123 "Ta-R0005RR" Ta-R0005RR 214,48.5 r90 top
R124 "Ta-R0005RR" Ta-R0005RR 212.5,48.5 r90 top
R125 "Ta-R0005RR" Ta-R0005RR 205.5,45 r90 top
R126 "Ta-R0005RR" Ta-R0005RR 211,48.5 r90 top
R127 "Ta-R0005RR" Ta-R0005RR 205.5,41.5 r90 top
R128 "Ta-R0005RR" Ta-R0005RR 205.5,38.5 r90 top
R129 "Ta-R0005RR" Ta-R0005RR 205.5,35.5 r90 top
R130 "Ta-R0005RR" Ta-R0005RR 152,48.5 r90 top
R131 "Ta-R0005RR" Ta-R0005RR 150.5,48.5 r90 top
R132 "Ta-R0005RR" Ta-R0005RR 149.1,48.5 r90 top
R133 "Ta-R0005RR" Ta-R0005RR 196.6,43.5 r90 top
R134 "Ta-R0005RR" Ta-R0005RR 198,41.5 r90 top
R135 "Ta-R0005RR" Ta-R0005RR 198,38.5 r90 top
R136 "Ta-R0005RR" Ta-R0005RR 198,35.5 r90 top
R137 "Ta-R0005RR" Ta-R0005RR 90,48.5 r90 top
R138 "Ta-R0005RR" Ta-R0005RR 88.5,48.5 r90 top
R139 "Ta-R0005RR" Ta-R0005RR 55,44.5 r180 top
R140 "Ta-R0005RR" Ta-R0005RR 87,48.5 r90 top
R141 "Ta-R0005RR" Ta-R0005RR 58,44.5 r180 top
R142 "Ta-R0005RR" Ta-R0005RR 64.1,46.3 r270 top
R143 "Ta-R0005RR" Ta-R0005RR 66.2,45.9 r180 top
R144 "Ta-R0005RR" Ta-R0005RR 40.5,106.5 r0 top
R145 "Ta-R0005RR" Ta-R0005RR 40.5,108 r0 top
R146 "Ta-R0005RR" Ta-R0005RR 39.5,110.5 r90 top
R147 "Ta-R0005RR" Ta-R0005RR 54.5,35.5 r180 top
R148 "Ta-R0005RR" Ta-R0005RR 72.5,49 r90 top
R149 "Ta-R0005RR" Ta-R0005RR 71,49 r90 top
R150 "Ta-R0005RR" Ta-R0005RR 49,44 r180 top
R151 "Ta-R0005RR" Ta-R0005RR 46.5,48.3 r180 top
R152 "Ta-R0005RR" Ta-R0005RR 44,40 r90 top
R153 "Ta-R0005RR" Ta-R0005RR 48.5,36 r0 top
R154 "Ta-R0005RR" Ta-R0005RR 52,40 r270 top
R155 "Ta-R0005RR" Ta-R0005RR 49.5,34.5 r180 top
R156 "Ta-R0005RR" Ta-R0005RR 45.5,40.5 r90 top
R157 "Ta-R0005RR" Ta-R0005RR 49.5,33 r0 top
R158 "Ta-R0008RR" Ta-R0008RR 126,100 r180 bottom
R159 "Ta-R0008RR" Ta-R0008RR 188,100 r180 bottom
R160 "Ta-R0008RR" Ta-R0008RR 250,100 r180 bottom
R161 "Ta-R0005RR" Ta-R0005RR 27,105.5 r90 top
R162 "Ta-R0005RR" Ta-R0005RR 125.7,37.2 r270 top
R163 "Ta-R0005RR" Ta-R0005RR 119.5,39.8 r270 top
R164 "Ta-R0005RR" Ta-R0005RR 112.7,41.9 r270 top
R165 "Ta-R0005RR" Ta-R0005RR 97.8,48.5 r0 top
R166 "Ta-R0003RR" Ta-R0003RR 100,64 r90 top
R167 "Ta-R0005RR" Ta-R0005RR 125.8,44 r180 top
R168 "Ta-R0005RR" Ta-R0005RR 122.8,48.5 r0 top
R169 "Ta-R0003RR" Ta-R0003RR 125,64 r90 top
R170 "Ta-R0005RR" Ta-R0005RR 133.1,38.2 r270 top
R171 "Ta-R0005RR" Ta-R0005RR 127.3,40.3 r270 top
R172 "Ta-R0005RR" Ta-R0005RR 130.4,45.1 r0 top
R173 "Ta-R0005RR" Ta-R0005RR 159.8,48.5 r0 top
R174 "Ta-R0003RR" Ta-R0003RR 162,64 r90 top
R175 "Ta-R0005RR" Ta-R0005RR 133.3,45.6 r180 top
R176 "Ta-R0005RR" Ta-R0005RR 184.8,48.5 r0 top
R177 "Ta-R0003RR" Ta-R0003RR 187,64 r90 top
R178 "Ta-R0005RR" Ta-R0005RR 140.5,38.2 r0 top
R179 "Ta-R0005RR" Ta-R0005RR 135.8,36.6 r0 top
R180 "Ta-R0005RR" Ta-R0005RR 139.8,44.8 r180 top
R181 "Ta-R0005RR" Ta-R0005RR 221.8,48.5 r0 top
R182 "Ta-R0003RR" Ta-R0003RR 224,64 r90 top
R183 "Ta-R0005RR" Ta-R0005RR 142.9,41.5 r270 top
R184 "Ta-R0005RR" Ta-R0005RR 246.8,48.5 r0 top
R185 "Ta-R0003RR" Ta-R0003RR 249,64 r90 top
R186 "Ta-R0003RR" Ta-R0003RR 33,45.1 r270 top
R187 "Ta-R0003RR" Ta-R0003RR 34.8,45.1 r90 top
R188 "Ta-R0003RR" Ta-R0003RR 34.8,41.2 r90 top
R189 "Ta-R0003RR" Ta-R0003RR 60.3,40.5 r90 top
R190 "Ta-R0003RR" Ta-R0003RR 70.3,41.8 r90 top
T1 "Ta-T0001DD" Ta-T0001DD 51.5,151 r0 top
TP1 "Ta-TP0002RR" Ta-TP0002RR 94,76 r90 top
TP2 "Ta-TP0002RR" Ta-TP0002RR 156,76 r90 top
TP3 "Ta-TP0002RR" Ta-TP0002RR 218,76 r90 top
TP4 "Ta-TP0002RR" Ta-TP0002RR 100,61 r90 top
TP5 "Ta-TP0002RR" Ta-TP0002RR 102,73 r0 top
TP6 "Ta-TP0002RR" Ta-TP0002RR 93.5,73 r90 top
TP7 "Ta-TP0002RR" Ta-TP0002RR 125,61 r90 top
TP8 "Ta-TP0002RR" Ta-TP0002RR 127,73 r0 top
TP9 "Ta-TP0002RR" Ta-TP0002RR 117,73 r90 top
TP10 "Ta-TP0002RR" Ta-TP0002RR 162,61 r90 top
TP11 "Ta-TP0002RR" Ta-TP0002RR 164,73 r0 top
TP12 "Ta-TP0002RR" Ta-TP0002RR 155.5,73 r90 top
TP13 "Ta-TP0002RR" Ta-TP0002RR 187,61 r90 top
TP14 "Ta-TP0002RR" Ta-TP0002RR 189,73 r0 top
TP15 "Ta-TP0002RR" Ta-TP0002RR 179,73 r90 top
TP16 "Ta-TP0002RR" Ta-TP0002RR 224,61 r90 top
TP17 "Ta-TP0002RR" Ta-TP0002RR 226,73 r0 top
TP18 "Ta-TP0002RR" Ta-TP0002RR 217.5,73 r90 top
TP19 "Ta-TP0002RR" Ta-TP0002RR 249,61 r90 top
TP20 "Ta-TP0002RR" Ta-TP0002RR 251,73 r0 top
TP21 "Ta-TP0002RR" Ta-TP0002RR 241,73 r90 top
TP22 "Ta-TP0001DD" Ta-TP0001DD 23,125 r90 top
TP23 "Ta-TP0001DD" Ta-TP0001DD 34.5,114 r90 top
TP24 "Ta-TP0001DD" Ta-TP0001DD 39.5,129 r90 top
TP25 "Ta-TP0001DD" Ta-TP0001DD 31,130.5 r90 top
TP26 "Ta-TP0001DD" Ta-TP0001DD 33,139 r90 top
TP27 "Ta-TP0001DD" Ta-TP0001DD 24.3,117.6 r270 top
TP28 "Ta-TP0001DD" Ta-TP0001DD 23.5,101.5 r270 top
TP29 "Ta-TP0001DD" Ta-TP0001DD 80.7,119.5 r270 top
TP30 "Ta-TP0001DD" Ta-TP0001DD 77.2,119.5 r270 top
TP31 "Ta-TP0001DD" Ta-TP0001DD 73.7,119.5 r270 top
TP32 "Ta-TP0001DD" Ta-TP0001DD 70.2,119.5 r270 top
TP33 "Ta-TP0001DD" Ta-TP0001DD 108.5,144 r0 top
TP34 "Ta-TP0001DD" Ta-TP0001DD 108.5,140.5 r0 top
TP35 "Ta-TP0001DD" Ta-TP0001DD 108.5,137 r0 top
TP36 "Ta-TP0001DD" Ta-TP0001DD 108.5,133.5 r0 top
TP37 "Ta-TP0001DD" Ta-TP0001DD 108.5,161.2 r0 top
TP38 "Ta-TP0001DD" Ta-TP0001DD 108.5,157.7 r0 top
TP39 "Ta-TP0001DD" Ta-TP0001DD 108.5,154.2 r0 top
TP40 "Ta-TP0001DD" Ta-TP0001DD 108.5,150.7 r0 top
TP41 "Ta-TP0001DD" Ta-TP0001DD 63.5,119.5 r270 top
TP42 "Ta-TP0001DD" Ta-TP0001DD 60,119.5 r270 top
TP43 "Ta-TP0001DD" Ta-TP0001DD 56.5,119.5 r270 top
TP44 "Ta-TP0001DD" Ta-TP0001DD 53,119.5 r270 top
TP45 "Ta-TP0001DD" Ta-TP0001DD 61.5,46.5 r0 top
TP46 "Ta-TP0001DD" Ta-TP0001DD 208.5,35 r270 top
TP47 "Ta-TP0001DD" Ta-TP0001DD 195,35 r270 top
TP48 "Ta-TP0001DD" Ta-TP0001DD 57.5,35 r0 top
TP49 "Ta-TP0001DD" Ta-TP0001DD 66,43 r270 top
TP50 "Ta-TP0001DD" Ta-TP0001DD 64.5,71 r270 top
TP51 "Ta-TP0001DD" Ta-TP0001DD 94,27.5 r180 top
TP52 "Ta-TP0001DD" Ta-TP0001DD 94,31.5 r180 top
TP53 "Ta-TP0001DD" Ta-TP0001DD 79.5,30.5 r180 top
TP54 "Ta-TP0001DD" Ta-TP0001DD 84.5,23.5 r180 top
TP55 "Ta-TP0001DD" Ta-TP0001DD 86.5,37.8 r180 top
TP56 "Ta-TP0001DD" Ta-TP0001DD 46,33 r270 top
TP57 "Ta-TP0001DD" Ta-TP0001DD 104.5,33 r0 top
TP58 "Ta-TP0001DD" Ta-TP0001DD 115.5,30.5 r0 top
TP59 "Ta-TP0001DD" Ta-TP0001DD 171.5,31.5 r180 top
TP60 "Ta-TP0001DD" Ta-TP0001DD 181.5,40 r180 top
TP61 "Ta-TP0001DD" Ta-TP0001DD 173.5,41 r180 top
TP62 "Ta-TP0001DD" Ta-TP0001DD 123,30 r0 top
TP63 "Ta-TP0001DD" Ta-TP0001DD 127,30 r0 top
TP64 "Ta-TP0001DD" Ta-TP0001DD 131,30 r0 top
TP65 "Ta-TP0001DD" Ta-TP0001DD 123,34 r0 top
TP66 "Ta-TP0001DD" Ta-TP0001DD 127,34 r0 top
TP67 "Ta-TP0001DD" Ta-TP0001DD 131,34 r0 top
TP68 "Ta-TP0001DD" Ta-TP0001DD 119,30 r180 top
TP69 "Ta-TP0001DD" Ta-TP0001DD 35.5,68.5 r270 top
TP70 "Ta-TP0001DD" Ta-TP0001DD 37.5,48.3 r0 top
TP71 "Ta-TP0001DD" Ta-TP0001DD 35.5,58 r270 top
TP72 "Ta-TP0001DD" Ta-TP0001DD 37.5,44.1 r0 top
TP73 "Ta-TP0001DD" Ta-TP0001DD 35.5,36 r0 top
TP74 "Ta-TP0001DD" Ta-TP0001DD 25.5,129 r0 top
ZD1 "Ta-D0008RR" Ta-D0008RR 71.2,129.5 r180 top
ZD2 "Ta-D0008RR" Ta-D0008RR 98.5,134.5 r270 top
ZD3 "Ta-D0008RR" Ta-D0008RR 98.5,151.7 r270 top
ZD4 "Ta-D0008RR" Ta-D0008RR 54,129.5 r180 top

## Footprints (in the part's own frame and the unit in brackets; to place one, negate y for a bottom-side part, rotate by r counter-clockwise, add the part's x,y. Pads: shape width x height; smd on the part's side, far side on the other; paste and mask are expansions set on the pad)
Logo-Toshiba [mm] "KC00080BKP"
Ta-C0001RR [mm] "KC00080BKP"
  rect 0.8x0.9 smd paste-1 mask+0: 1(-0.75,0) 2(0.75,0)
  silkscreen extent -0.06,-0.5 0.06,0.5
Ta-C0002RR [mm] "KC00080BKP"
  rect 1x1.2 smd paste-1.3 mask+0: 1(-1,0) 2(1,0)
  silkscreen extent -0.25,-0.72 0.25,0.73
Ta-C0003RR#1 [mm] "KC00080BKP"
  rect 1x5 smd paste-5.1 mask+0: 1(2.8,0) 2(-2.8,0)
  silkscreen extent -2.03,-2.6 2.03,2.6
Ta-C0003RR#2 [mm] "KC00080BKP"
  rect 1x5 smd paste-5.1 mask+0: 1(-2.8,0) 2(2.8,0)
  silkscreen extent -2.03,-2.6 2.03,2.6
Ta-C0004DD-4P [mm] "KC00080BKP"
  round 2 / inner round 1.9 / far side round 2 hole 1.4 paste-2.2 mask+0: 1(-18.75,5.1) 2(-18.75,-5.1) 3(18.75,5.1) 4(18.75,-5.1)
  silkscreen extent -20.6,-13.1 20.6,13.1
Ta-C0004RR [mm] "KC00080BKP"
  rect 1.45x5 smd paste-5.1 mask+0: 1(-3.025,0) 2(3.025,0)
  silkscreen extent -2.03,-2.6 2.03,2.6
Ta-CN0002DD [mm] "KC00080BKP"
  round 2 / inner round 1.5 / far side round 2 hole 1 paste-2.2 mask+0: 1(-4.5,-1.3) 2(-1,-1.3) 3(2.5,-1.3) 4(6,-1.3)
  silkscreen extent -7.85,-6.1 7.85,6.1
Ta-CN0004DD(OT-005+OT-006) [mm] "KC00080BKP"
  round 3.1 / inner round 3.2 / far side round 3.1 hole 2.1 paste-3.3 mask+0: 1(-2.5,-3.625) 2(2.5,-3.625) 3(2.5,3.625) 4(-2.5,3.625)
  silkscreen extent -4,-4.25 5.6,4.25
Ta-CN0005DDFy [mm] "KC00080BKP"
  rect 0.76x1.89 smd paste-1.99 mask+0: 1(12.065,-2.855) 2(12.065,-6.045) 3(10.795,-2.855) 4(10.795,-6.045) 5(9.525,-2.855) 6(9.525,-6.045) 7(8.255,-2.855) 8(8.255,-6.045) 9(6.985,-2.855) 10(6.985,-6.045) 11(5.715,-2.855) 12(5.715,-6.045) 13(4.445,-2.855) 14(4.445,-6.045) 15(3.175,-2.855) 16(3.175,-6.045) 17(1.905,-2.855) 18(1.905,-6.045) 19(0.635,-2.855) 20(0.635,-6.045) 21(-0.635,-2.855) 22(-0.635,-6.045) 23(-1.905,-2.855) 24(-1.905,-6.045) 25(-3.175,-2.855) 26(-3.175,-6.045) 27(-4.445,-2.855) 28(-4.445,-6.045) 29(-5.715,-2.855) 30(-5.715,-6.045) 31(-6.985,-2.855) 32(-6.985,-6.045) 33(-8.255,-2.855) 34(-8.255,-6.045) 35(-9.525,-2.855) 36(-9.525,-6.045) 37(-10.795,-2.855) 38(-10.795,-6.045) 39(-12.065,-2.855) 40(-12.065,-6.045)
  silkscreen extent -12.8,-1.36 12.8,-0.84
Ta-D0001RR [mm] "KC00080BKP"
  rect 0.6x0.8 smd paste-0.9 mask+0: A(0.85,0) C(-0.85,0)
  silkscreen extent -1.43,-0.67 1.43,0.67
Ta-D0002RR [mm] "KC00080BKP"
  rect 0.8x0.9 smd paste-1 mask+0: A(1.15,0) C(-1.15,0)
  silkscreen extent -1.85,-0.75 1.85,0.75
Ta-D0008RR [mm] "KC00080BKP"
  rect 0.9x0.95 smd paste-1.05 mask+0: A(1.575,0) C(-1.575,0)
  silkscreen extent -2.39,-0.91 2.39,0.91
Ta-ETC0001DDFy [mm] "KC00080BKP"
  round 2.2 / inner round 2.1 / far side round 2.2 hole 1.6 paste-2.4 mask+0: 1(-7.98,-7.7) 2(-2.54,0)
  round 2.2 hole 2 paste-2.2 mask+0: 3(2.72,-7.7)
  round 1.7 hole 1.6 paste-1.7 mask+0: 4(5.08,-7.7)
  round 2.2 hole 1.6 paste-2.2 mask+0: 5(7.62,-7.7)
  silkscreen extent -10.61,-2.39 10.61,2.83
Ta-ETC0003DD [mm] "KC00080BKP"
  round 2 hole 1 paste-2.2 mask+0: 1(0,0)
  silkscreen extent -1.36,-1.4 1.4,1.4
Ta-ETC0005DD [mm] "KC00080BKP"
  round 3.5 hole 2.5 paste-3.7 mask+0: 1(22.92,2.45) 2(-22.92,2.45)
  silkscreen extent -25.1,-8.32 25.1,9.88
Ta-FET0001RR [mm] "KC00080BKP"
  rect 0.5x1 smd paste-1.1 mask+0: D(0,0.95) G(-0.65,-0.95) S(0.65,-0.95)
  silkscreen extent -1.1,-0.72 1.1,0.72
Ta-FET0002RR [mm] "KC00080BKP"
  rect 0.62x0.7 smd paste-0.8 mask+0: 1(-0.95,-1.25) 2(0,-1.25) 3(0.95,-1.25) 4(0.95,1.25) 5(0,1.25) 6(-0.95,1.25)
  silkscreen extent -1.55,-1.9 1.55,1.9
Ta-IC0001DD [mm] "KC00080BKP"
  round 1.6 / inner round 1.5 / far side round 1.6 hole 1 paste-1.8 mask+0: 1(-2.54,-2.25) 2(0,-2.25) 3(2.54,-2.25)
  silkscreen extent -5.9,-4.35 5.9,4.35
Ta-IC0001RR [mm] "KC00080BKP"
  rect 0.8x1.8 smd paste-1.9 mask+0: 1(-1.905,-5.3) 2(-0.635,-5.3) 3(0.635,-5.3) 4(1.905,-5.3) 5(1.905,5.3) 6(0.635,5.3) 7(-0.635,5.3) 8(-1.905,5.3)
  silkscreen extent -3.03,-6.5 3.02,6.5
Ta-IC0003RR [mil] "KC00080BKP"
  rect 30x45 smd paste-48.94 mask+0: 1(-175,-185) 2(-125,-185) 3(-75,-185) 4(-25,-185) 5(25,-185) 6(75,-185) 7(125,-185) 8(175,-185) 9(175,185) 10(125,185) 11(75,185) 12(25,185) 13(-25,185) 14(-75,185) 15(-125,185) 16(-175,185)
  silkscreen extent -207,-220 207,220
Ta-IC0004RR [mm] "KC00080BKP"
  rect 0.62x1.22 smd paste-1.32 mask+0: 1(-0.95,-1.31) 2(0,-1.31) 3(0.95,-1.31) 4(0.95,1.31) 5(-0.95,1.31)
  silkscreen extent -1.55,-2.25 1.55,2.25
Ta-IC0005RR_70 [mm] "KC00080BKP"
  rect 0.8x1 smd paste-1.1 mask+0: 1(-0.95,-1.2) 3(0.95,-1.2) 4(0.95,1.2) 5(-0.95,1.2)
  rect 0.5x1 smd paste-1.1 mask+0: 2(0,-1.2)
  silkscreen extent -1.68,-2.02 1.67,2.02
Ta-IC0007RR [mm] "KC00080BKP"
  rect 0.8x1.3 smd paste-1.4 mask+0: 1(-1.27,-4.75) 2(0,-4.75) 3(1.27,-4.75) 4(1.27,4.75) 5(0,4.75) 6(-1.27,4.75)
  silkscreen extent -2.02,-5.7 2.02,5.7
Ta-IC0008RR_70 [mm] "KC00080BKP"
  rect 0.35x0.8 smd paste-0.9 mask+0: 1(-0.65,-0.95) 2(0,-0.95) 3(0.65,-0.95)
  rect 0.45x0.8 smd paste-0.9 mask+0: 4(0.65,0.95) 5(-0.65,0.95)
  silkscreen extent -1.2,-1.68 1.2,1.68
Ta-IC0009RR_70 [mm] "KC00080BKP"
  rect 0.35x0.9 smd paste-1 mask+0: 1(-0.975,-1.7) 2(-0.325,-1.7) 3(0.325,-1.7) 4(0.975,-1.7) 5(0.975,1.7) 6(0.325,1.7) 7(-0.325,1.7) 8(-0.975,1.7)
  silkscreen extent -1.55,-2.45 1.55,2.45
Ta-IC0010RR_70 [mm] "KC00080BKP"
  rect 0.65x1 smd paste-1.1 mask+0: 1(-0.95,-1.315) 2(0,-1.315) 3(0.95,-1.315)
  rect 0.66x1 smd paste-1.1 mask+0: 4(0.95,1.315) 5(-0.95,1.315)
  silkscreen extent -1.58,-2.11 1.58,2.12
Ta-J0002DD [mm] "KC00080BKP"
  round 0 / inner round 0.97 / far side round 0 hole 0.7 paste-1.6 mask+0: 1(-1.27,0) 2(0,0) 3(1.27,0)
  silkscreen extent -2,-1.15 2,1.15
Ta-L0001RRM [mm] "KC00080BKP"
  rect 2x1.2 smd paste-2.1 mask+0: 1(-3.75,-1.27) 2(-3.75,1.27) 3(3.75,1.27) 4(3.75,-1.27)
  silkscreen extent -4.7,-3.1 4.7,3.1
Ta-LED0001RR [mm] "KC00080BKP"
  rect 1.1x1.2 smd paste-1.3 mask+0: A(1.05,0) C(-1.05,0)
  silkscreen extent -1.9,-0.9 1.9,0.9
Ta-R0001RR_F [mm] "KC00080BKP"
  rect 3x4 smd paste-4.1 mask+0: 1(2.25,0) 2(-2.25,0)
  silkscreen extent -0.45,-1.7 0.45,1.7
Ta-R0003RR [mm] "KC00080BKP"
  rect 1x1.2 smd paste-1.3 mask+0: 1(-1,0) 2(1,0)
  silkscreen extent -0.25,-0.72 0.25,0.72
Ta-R0005RR [mm] "KC00080BKP"
  rect 0.8x0.9 smd paste-1 mask+0: 1(-0.75,0) 2(0.75,0)
  silkscreen extent -0.06,-0.5 0.06,0.5
Ta-R0006RR [mm] "KC00080BKP"
  rect 0.8x3.2 smd paste-3.3 mask+0: 1(-0.75,0) 2(0.75,0)
  silkscreen extent -0.08,-1.7 0.08,1.7
Ta-R0007RR [mm] "KC00080BKP"
  rect 1.25x3.2 smd paste-3.3 mask+0: 1(-2.925,0) 2(2.925,0)
  silkscreen extent -2.03,-1.7 2.03,1.7
Ta-R0008RR [mm] "KC00080BKP"
  rect 1.4x2.5 smd paste-2.6 mask+0: 1(2.5,0) 2(-2.5,0)
  silkscreen extent -1.53,-1.35 1.53,1.35
Ta-T0001DD [mm] "KC00080BKP"
  round 1.6 / inner round 1.5 / far side round 1.6 hole 1 paste-1.8 mask+0: 1(-8.89,-4.445) 2(1.27,-4.445) 3(3.81,-4.445) 4(8.89,-4.445) 5(8.89,-1.905) 6(8.89,1.905) 7(8.89,4.445) 8(3.81,4.445) 9(1.27,4.445) 10(-8.89,4.445)
  silkscreen extent -10.39,-6.19 10.38,6.19
Ta-TP0001DD [mm] "KC00080BKP"
  round 1.4 / inner round 1.3 / far side round 1.4 hole 0.8 paste-1.6 mask+0: 1(0,0)
  silkscreen extent -1.2,-1.2 1.2,1.2
Ta-TP0002RR [mm] "KC00080BKP"
  round 1.5 smd paste-1.6 mask+0: 1(0,0)
  silkscreen extent -1,-1 1,1

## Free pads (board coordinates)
  round 0 hole 3.5 unplated paste-3.5 mask+0: ""(25,25) ""(25,92.5) ""(25,160) ""(195,160)

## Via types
v1: diameter 1.6, hole 1, TOP to BOTTOM, 364 vias
v2: diameter 0.8, hole 0.3, TOP to BOTTOM, 68 vias
v3: diameter 8, hole 3.5, TOP to BOTTOM, 4 vias

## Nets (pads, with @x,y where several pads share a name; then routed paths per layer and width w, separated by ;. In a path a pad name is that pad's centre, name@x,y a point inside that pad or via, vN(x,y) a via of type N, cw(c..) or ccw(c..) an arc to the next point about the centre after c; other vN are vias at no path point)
ADB: C158.2 IC21.7 R92.2 R147.1 TP48.1 | length 64.2
  TOP w0.3: IC21.7@54.825,38.3 54.825,37.475 55.25,37.05 R147.1@55.25,35.5 C158.2@55.25,34.1 56.6,34.1 TP48.1@57.5,35 58.05,34.45 70.756,34.45 77.206,40.9 106.265,40.9 v2(106.75,41.1) ; v2(106.25,37.5) R92.2@107.5,37.5
  BOTTOM w0.3: v2(106.25,37.5) 106.75,38 v2(106.75,41.1)
ADU: C161.2 CN3.36 D31.A D32.C IC23.1 R143.1 TP49.1 | length 100.7
  TOP w0.3: IC23.1@63.975,41.7 63.975,44.175 C161.2@63.95,44.2 64.8,44.2 TP49.1@66,43 66.95,43.95 R143.1@66.95,45.9 ; v2(66.525,32.7) 70.75,32.7 77.7,39.65 99.2,39.65 102.35,36.5 D32.C@102.35,34.5 D31.A@102.35,32.5 103.3,31.55 v2(103.3,30.5) ; v2(128.7,27.4) 129.025,27.075 CN3.36@129.025,25.601 CN3.36@129.025,25.531
  Mid-Layer 2 w0.3: TP49.1@66,43 66.9,43 68.8,41.1 68.8,34.975 v2(66.525,32.7)
  BOTTOM w0.3: v2(103.3,30.5) 103.758,30.242 111.4,22.6 119.5,22.6 120.3,23.4 120.3,24.15 121,24.85 123.8,24.85 124.4,25.45 126.75,25.45 v2(128.7,27.4)
ADV: C156.2 CN3.38 D33.A D34.C IC22.7 R136.1 TP47.1 | length 119.8
  TOP w0.3: D34.C@102.35,30.5 D33.A@102.35,28.5 108.4,28.5 v2(109.7,27.2) ; CN3.38@130.295,25.531 CN3.38@130.295,25.601 130.295,26.886 v2(130.4,27.4) ; C156.2@196.6,37.75 196.6,36.6 TP47.1@195,35 196.02,34.75 R136.1@198,34.75 198.7,34.75 198.9,34.95 198.9,36.525 199.05,36.675 IC22.7@199.8,36.675
  BOTTOM w0.3: v2(109.7,27.2) 111.75,25.15 119.6,25.15 120.55,26.1 123.35,26.1 123.9,26.65 125.97,26.65 128.12,28.8 129.351,28.8 130.4,27.751 v2(130.4,27.4) 130.625,27.875 130.95,28.2 131.8,28.2 133.9,30.3 133.9,31.2 139.85,37.15 170.45,37.15 172.7,39.4 175,39.4 182.1,32.3 187.4,32.3 188.6,33.5 193.5,33.5 TP47.1@195,35
ADV2: C152.2 IC20.7 R133.1 R134.2 | length 6.1
  TOP w0.3: R133.1@196.6,42.75 197.1,42.25 R134.2@198,42.25 C152.2@198,44.25 198.8,44.25 198.9,44.35 198.9,44.95 199.125,45.175 IC20.7@199.8,45.175
ADW: C155.2 CN3.40 D35.A D36.C IC22.1 R129.1 TP46.1 | length 137.2
  TOP w0.3: D35.A@102.35,24.5 D36.C@102.35,26.5 103.55,27.7 108,27.7 v2(108.5,27.2) ; v2(131.5,27.4) 131.565,26.879 CN3.40@131.565,25.601 CN3.40@131.565,25.531 ; IC22.1@203.2,36.025 204.125,36.025 204.4,35.75 204.4,34.95 204.6,34.75 R129.1@205.5,34.75 207.48,34.75 TP46.1@208.5,35 208.5,36.15 C155.2@206.9,37.75
  BOTTOM w0.3: v2(108.5,27.2) 108.5,26.35 111.65,23.2 119.2,23.2 119.7,23.7 119.7,24.4 120.75,25.45 123.55,25.45 124.15,26.05 126.219,26.05 128.369,28.2 129.031,28.2 129.6,27.631 129.6,26.9 129.95,26.55 130.85,26.55 131.242,26.942 v2(131.5,27.4) 131.9,27.4 134.5,30 134.5,30.95 140.1,36.55 170.75,36.55 173,38.8 174.7,38.8 183,30.5 204,30.5 TP46.1@208.5,35
BRK: CN3.19 R110.2 TP68.1 | length 11.4
  TOP w0.3: CN3.19@118.865,22.481 v2(118.865,24.006) ; TP68.1@119,30 R110.2@119,32.8 R110.2@119,33
  Mid-Layer 2 w0.3: v2(118.865,24.006) 117.85,25.021 117.85,28.85 TP68.1@119,30
G_UH: C137.2 D1.A D2.C Q1.1 Q1.5 R14.1 R15.1 R25.1 TP5.1 | length 35.5
  TOP w0.8: R14.1@100,69 100.15,69.15 D2.C@100.15,71 100.15,71.8 100.25,71.9 R25.1@100.25,73 TP5.1@102,73 ; Q1.5@100.62,79.3 100.62,77.68 101.25,77.05 C137.2@101.25,75 102,74.25 TP5.1@102,73 ; R15.1@102,69 101.85,69.15 D1.A@101.85,71 101.85,71.885 TP5.1@102,73
  Mid-Layer 2 w1.5: Q1.1@85.02,79.3 87.92,76.4 98.9,76.4 100.62,78.12 Q1.5@100.62,79.3
G_UL: C138.2 D3.A D4.C Q2.1 Q2.5 R17.1 R18.1 R26.1 TP8.1 | length 35.1
  TOP w0.8: R17.1@125,69 125.15,69.15 D4.C@125.15,71 125.15,71.8 125.25,71.9 R26.1@125.25,73 TP8.1@127,73 ; Q2.5@125.62,79.3 125.62,77.68 126.25,77.05 C138.2@126.25,75 127,74.25 TP8.1@127,73 ; R18.1@127,69 126.85,69.15 D3.A@126.85,71 126.85,71.885 TP8.1@127,73
  Mid-Layer 2 w1.5: Q2.1@110.02,79.3 112.42,76.9 124.4,76.9 125.62,78.12 Q2.5@125.62,79.3
G_VH: C141.2 D5.A D6.C Q3.1 Q3.5 R31.1 R32.1 R36.1 TP11.1 | length 35.5
  TOP w0.8: R31.1@162,69 162.15,69.15 D6.C@162.15,71 162.15,71.8 162.25,71.9 R36.1@162.25,73 TP11.1@164,73 ; Q3.5@162.62,79.3 162.62,77.68 163.25,77.05 C141.2@163.25,75 164,74.25 TP11.1@164,73 ; R32.1@164,69 163.85,69.15 D5.A@163.85,71 163.85,71.885 TP11.1@164,73
  Mid-Layer 2 w1.5: Q3.1@147.02,79.3 149.92,76.4 160.9,76.4 162.62,78.12 Q3.5@162.62,79.3
G_VL: C143.2 D7.A D8.C Q4.1 Q4.5 R34.1 R35.1 R37.1 TP14.1 | length 35.1
  TOP w0.8: R34.1@187,69 187.15,69.15 D8.C@187.15,71 187.15,71.8 187.25,71.9 R37.1@187.25,73 TP14.1@189,73 ; Q4.5@187.62,79.3 187.62,77.68 188.25,77.05 C143.2@188.25,75 189,74.25 TP14.1@189,73 ; R35.1@189,69 188.85,69.15 D7.A@188.85,71 188.85,71.885 TP14.1@189,73
  Mid-Layer 2 w1.5: Q4.1@172.02,79.3 174.42,76.9 186.4,76.9 187.62,78.12 Q4.5@187.62,79.3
